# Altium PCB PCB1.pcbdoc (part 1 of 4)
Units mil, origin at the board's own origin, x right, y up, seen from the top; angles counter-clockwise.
Board outline 6180 x 7065 mil, 2 copper layers (Top Layer, Bottom Layer); 471 components, 245 nets, 1464 pads, 505 vias.
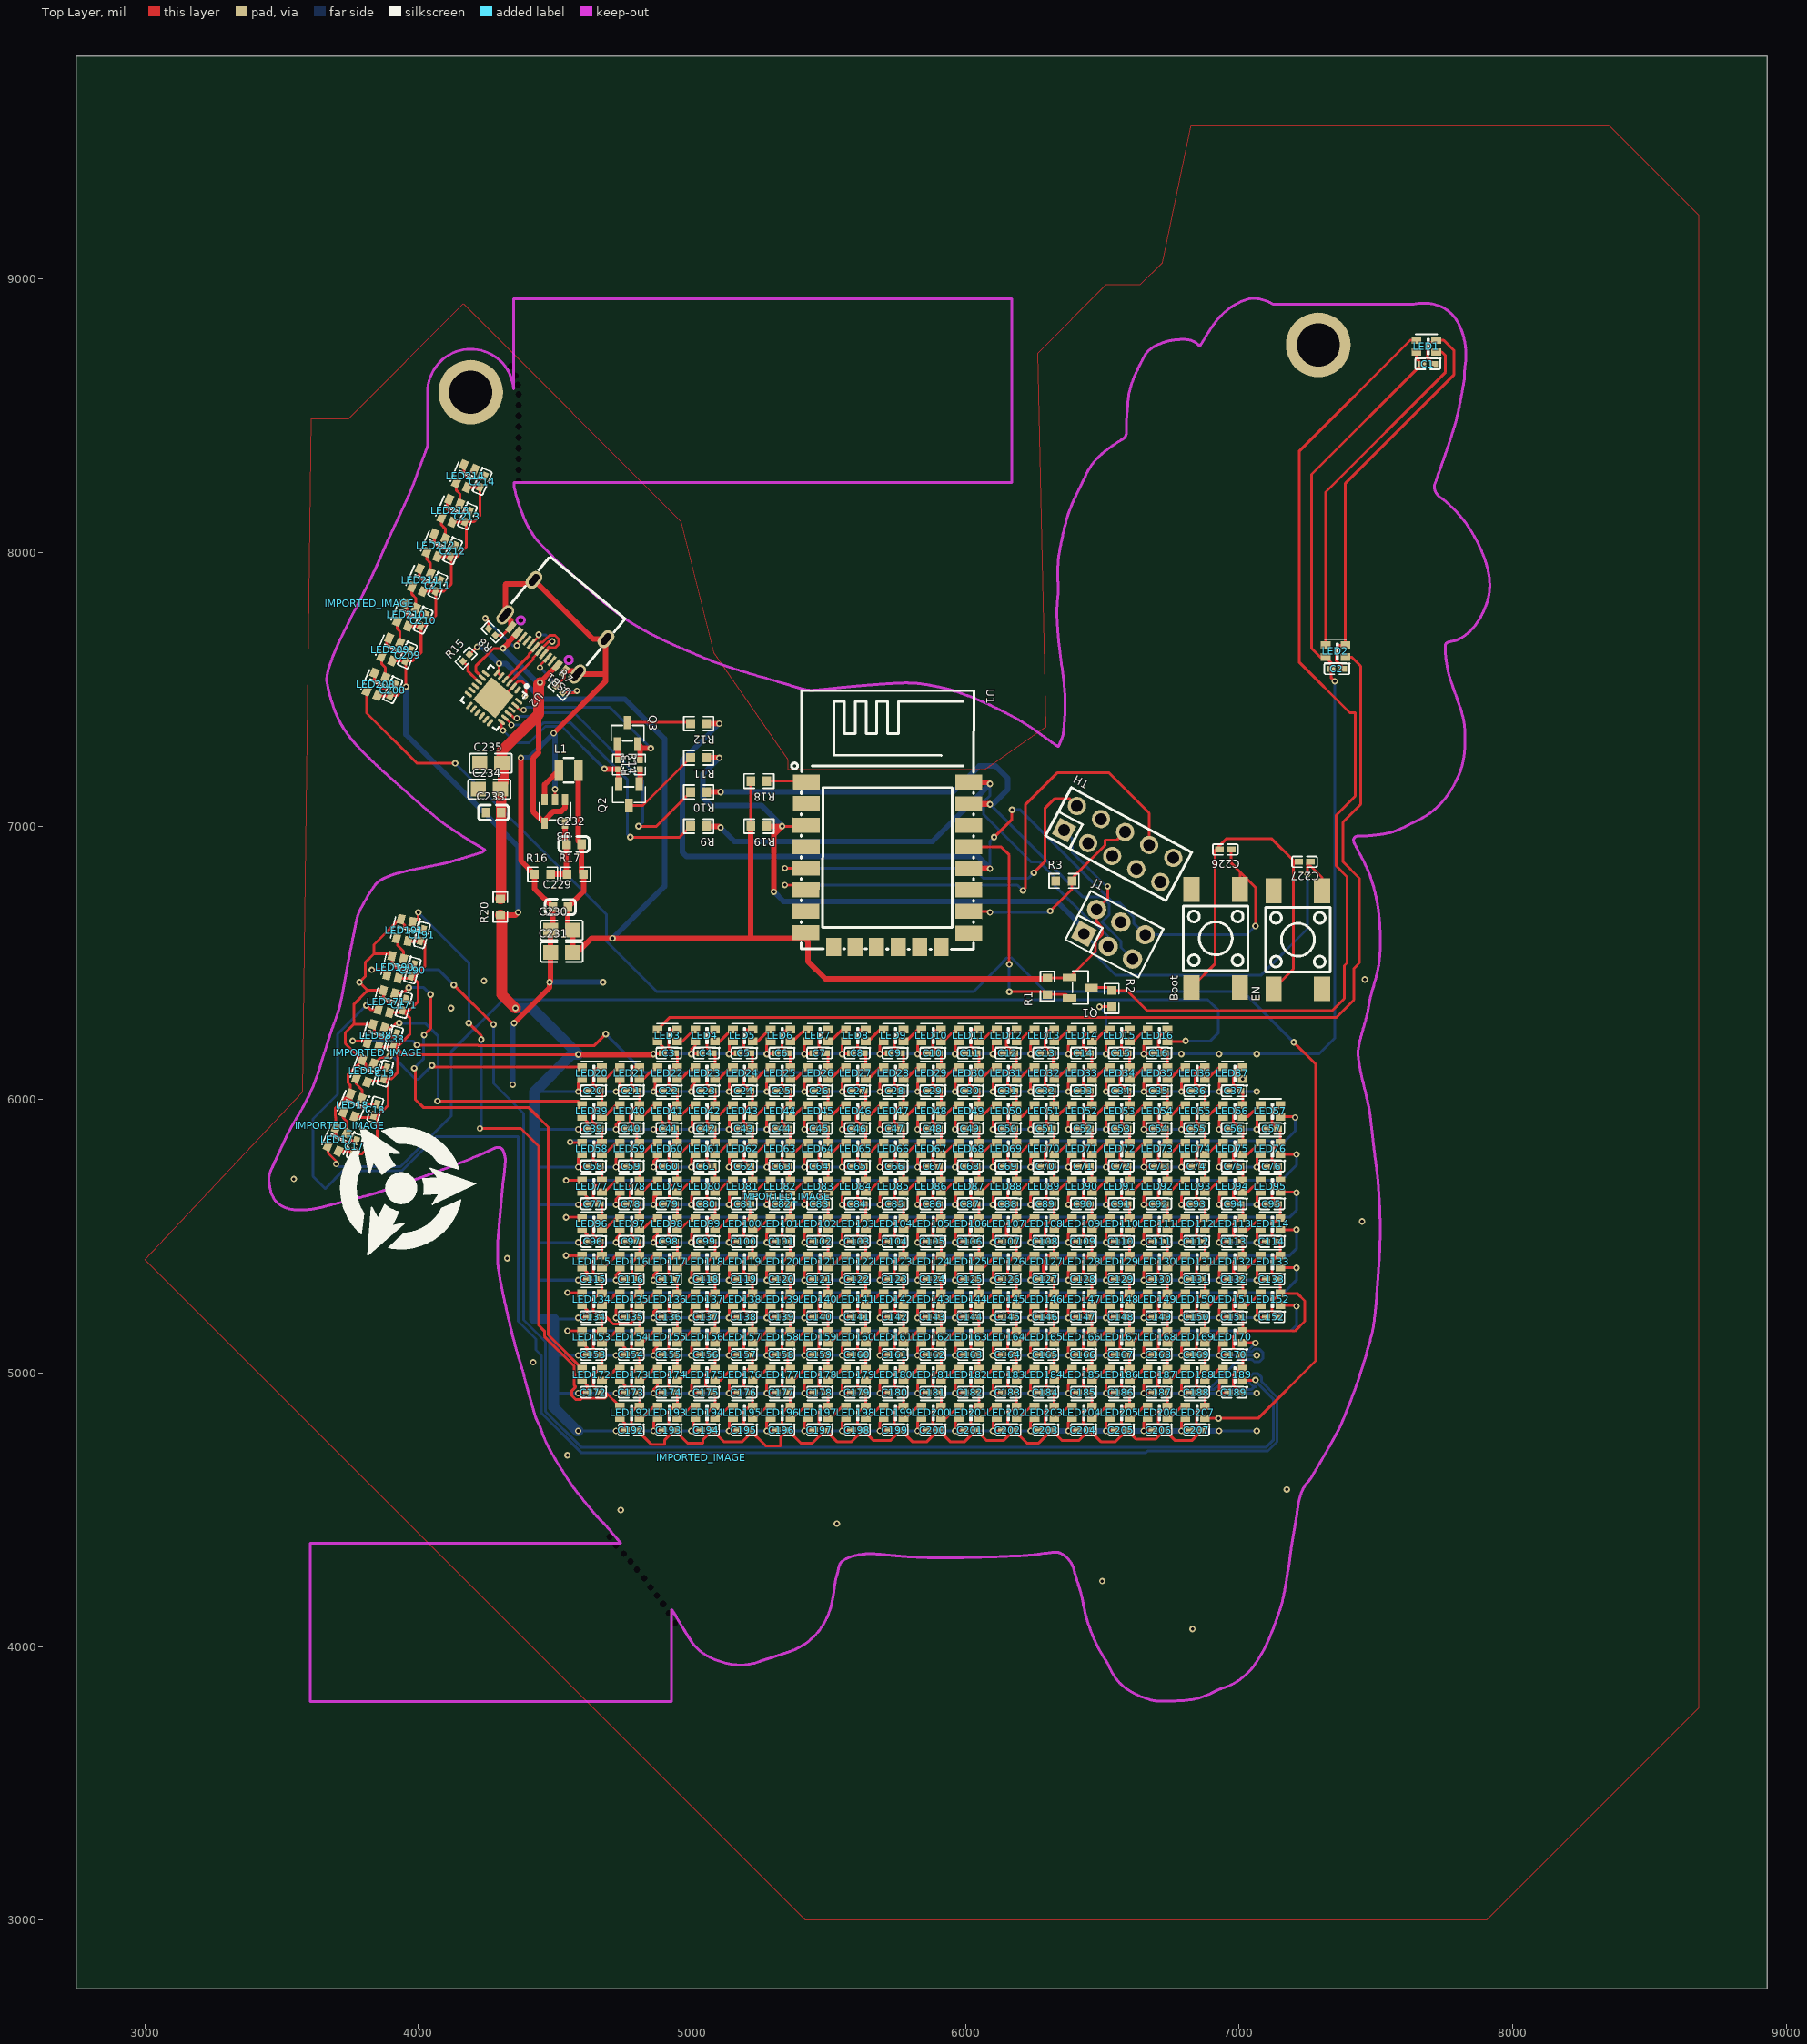
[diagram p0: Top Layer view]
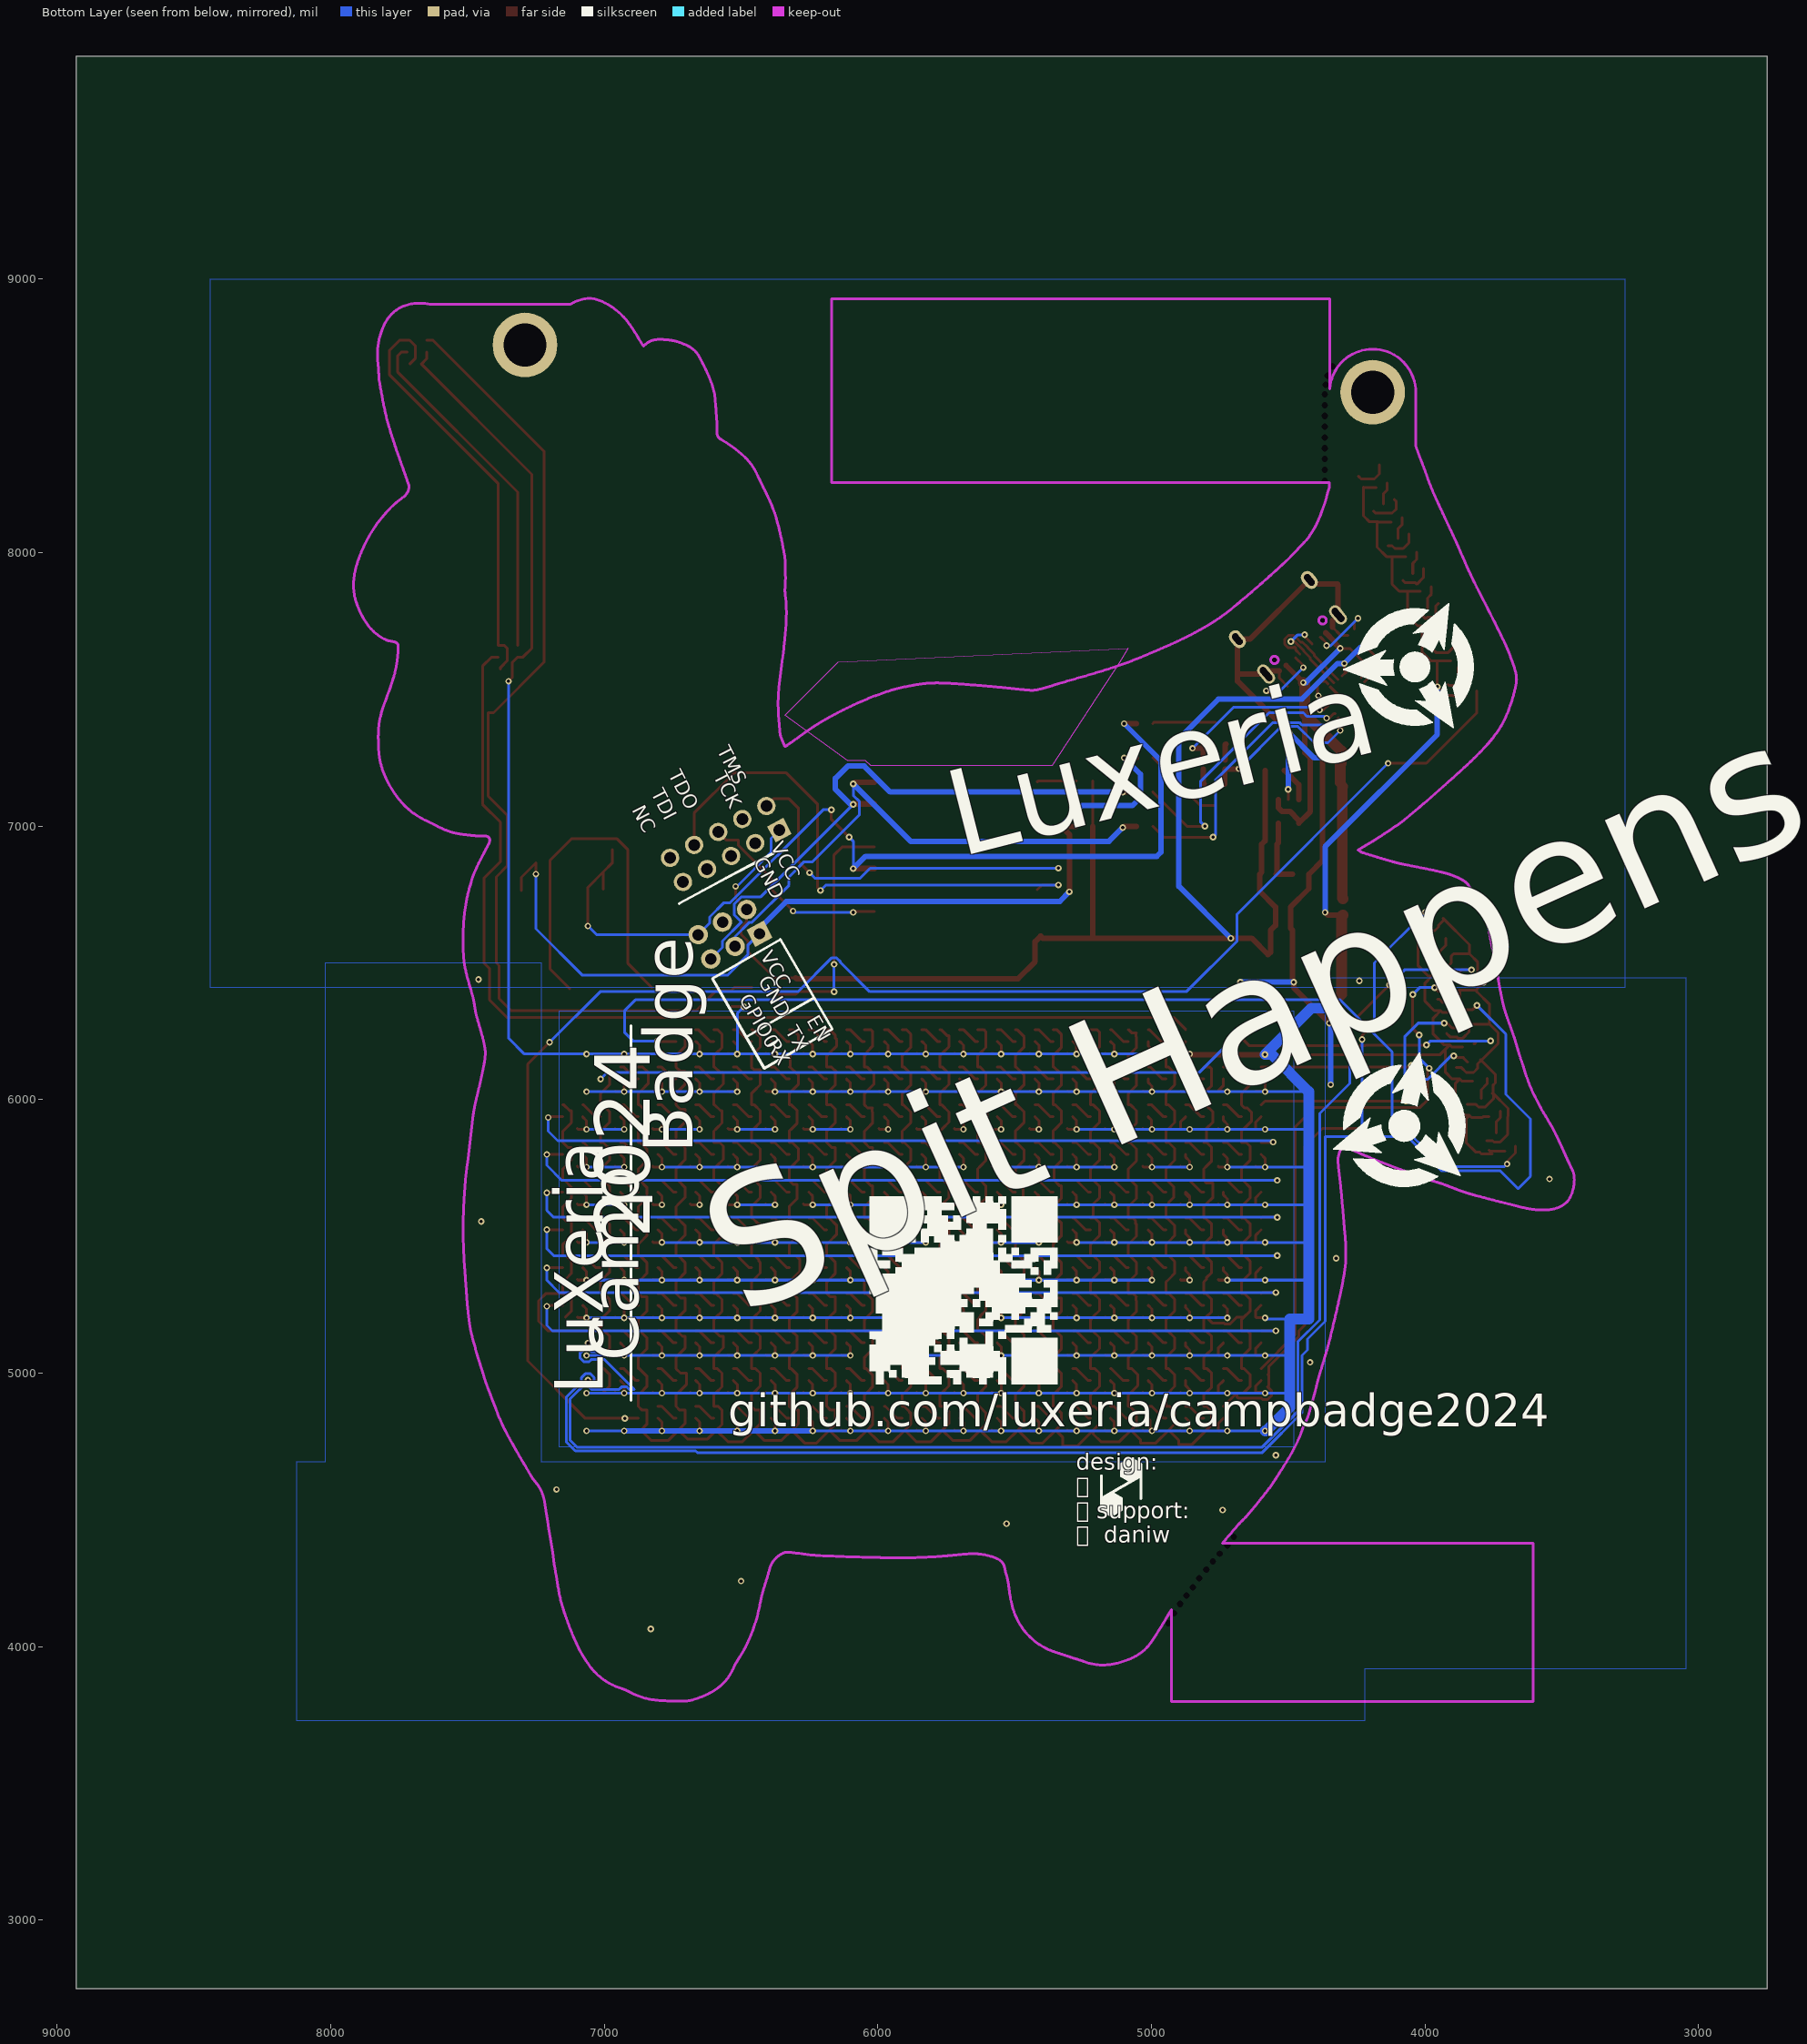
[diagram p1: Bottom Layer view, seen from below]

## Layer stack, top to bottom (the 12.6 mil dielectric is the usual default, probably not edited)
Top Layer: signal copper (thickness not stored)
Dielectric: dielectric 12.6, FR-4, Dk 4.8
Bottom Layer: signal copper (thickness not stored)

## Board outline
8930,2750 2750,2750 2750,9815 8930,9815

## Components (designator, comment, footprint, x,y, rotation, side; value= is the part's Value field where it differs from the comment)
Boot "TS-1002S-04526C" SW-SMD_4P-L6.0-W6.0-P4.50-LS9.0-2 6915,6590 r90 top
C1 "100nF" C0402 7690,8690 r180 top
C2 "CC0402KRX7R5BB104" C0402 7357.8,7575 r180 top
C3 "CC0402KRX7R5BB104" C0402 4915.59,6170 r180 top
C4 "CC0402KRX7R5BB104" C0402 5053.39,6170 r180 top
C5 "CC0402KRX7R5BB104" C0402 5191.18,6170 r180 top
C6 "CC0402KRX7R5BB104" C0402 5328.98,6170 r180 top
C7 "CC0402KRX7R5BB104" C0402 5466.77,6170 r180 top
C8 "CC0402KRX7R5BB104" C0402 5604.57,6170 r180 top
C9 "CC0402KRX7R5BB104" C0402 5742.36,6170 r180 top
C10 "CC0402KRX7R5BB104" C0402 5880.16,6170 r180 top
C11 "CC0402KRX7R5BB104" C0402 6017.95,6170 r180 top
C12 "CC0402KRX7R5BB104" C0402 6155.75,6170 r180 top
C13 "CC0402KRX7R5BB104" C0402 6293.54,6170 r180 top
C14 "CC0402KRX7R5BB104" C0402 6431.34,6170 r180 top
C15 "CC0402KRX7R5BB104" C0402 6569.13,6170 r180 top
C16 "CC0402KRX7R5BB104" C0402 6706.93,6170 r180 top
C17 "CC0402KRX7R5BB104" C0402 3767.86,5829.31 r255 top
C18 "CC0402KRX7R5BB104" C0402 3842.97,5963.18 r255 top
C19 "CC0402KRX7R5BB104" C0402 3878.62,6096.28 r255 top
C20 "CC0402KRX7R5BB104" C0402 4640,6032.2 r180 top
C21 "CC0402KRX7R5BB104" C0402 4777.8,6032.2 r180 top
C22 "CC0402KRX7R5BB104" C0402 4915.59,6032.2 r180 top
C23 "CC0402KRX7R5BB104" C0402 5053.39,6032.2 r180 top
C24 "CC0402KRX7R5BB104" C0402 5191.18,6032.2 r180 top
C25 "CC0402KRX7R5BB104" C0402 5328.98,6032.2 r180 top
C26 "CC0402KRX7R5BB104" C0402 5466.77,6032.2 r180 top
C27 "CC0402KRX7R5BB104" C0402 5604.57,6032.2 r180 top
C28 "CC0402KRX7R5BB104" C0402 5742.36,6032.2 r180 top
C29 "CC0402KRX7R5BB104" C0402 5880.16,6032.2 r180 top
C30 "CC0402KRX7R5BB104" C0402 6017.95,6032.2 r180 top
C31 "CC0402KRX7R5BB104" C0402 6155.75,6032.2 r180 top
C32 "CC0402KRX7R5BB104" C0402 6293.54,6032.2 r180 top
C33 "CC0402KRX7R5BB104" C0402 6431.34,6032.2 r180 top
C34 "CC0402KRX7R5BB104" C0402 6569.13,6032.2 r180 top
C35 "CC0402KRX7R5BB104" C0402 6706.93,6032.2 r180 top
C36 "CC0402KRX7R5BB104" C0402 6844.72,6032.2 r180 top
C37 "CC0402KRX7R5BB104" C0402 6982.52,6032.2 r180 top
C38 "CC0402KRX7R5BB104" C0402 3914.96,6221.13 r255 top
C39 "CC0402KRX7R5BB104" C0402 4640,5894.41 r180 top
C40 "CC0402KRX7R5BB104" C0402 4777.8,5894.41 r180 top
C41 "CC0402KRX7R5BB104" C0402 4915.59,5894.41 r180 top
C42 "CC0402KRX7R5BB104" C0402 5053.39,5894.41 r180 top
C43 "CC0402KRX7R5BB104" C0402 5191.18,5894.41 r180 top
C44 "CC0402KRX7R5BB104" C0402 5328.98,5894.41 r180 top
C45 "CC0402KRX7R5BB104" C0402 5466.77,5894.41 r180 top
C46 "CC0402KRX7R5BB104" C0402 5604.57,5894.41 r180 top
C47 "CC0402KRX7R5BB104" C0402 5742.36,5894.41 r180 top
C48 "CC0402KRX7R5BB104" C0402 5880.16,5894.41 r180 top
C49 "CC0402KRX7R5BB104" C0402 6017.95,5894.41 r180 top
C50 "CC0402KRX7R5BB104" C0402 6155.75,5894.41 r180 top
C51 "CC0402KRX7R5BB104" C0402 6293.54,5894.41 r180 top
C52 "CC0402KRX7R5BB104" C0402 6431.34,5894.41 r180 top
C53 "CC0402KRX7R5BB104" C0402 6569.13,5894.41 r180 top
C54 "CC0402KRX7R5BB104" C0402 6706.93,5894.41 r180 top
C55 "CC0402KRX7R5BB104" C0402 6844.72,5894.41 r180 top
C56 "CC0402KRX7R5BB104" C0402 6982.52,5894.41 r180 top
C57 "CC0402KRX7R5BB104" C0402 7120.31,5894.41 r180 top
C58 "CC0402KRX7R5BB104" C0402 4640,5756.61 r180 top
C59 "CC0402KRX7R5BB104" C0402 4777.8,5756.61 r180 top
C60 "CC0402KRX7R5BB104" C0402 4915.59,5756.61 r180 top
C61 "CC0402KRX7R5BB104" C0402 5053.39,5756.61 r180 top
C62 "CC0402KRX7R5BB104" C0402 5191.18,5756.61 r180 top
C63 "CC0402KRX7R5BB104" C0402 5328.98,5756.61 r180 top
C64 "CC0402KRX7R5BB104" C0402 5466.77,5756.61 r180 top
C65 "CC0402KRX7R5BB104" C0402 5604.57,5756.61 r180 top
C66 "CC0402KRX7R5BB104" C0402 5742.36,5756.61 r180 top
C67 "CC0402KRX7R5BB104" C0402 5880.16,5756.61 r180 top
C68 "CC0402KRX7R5BB104" C0402 6017.95,5756.61 r180 top
C69 "CC0402KRX7R5BB104" C0402 6155.75,5756.61 r180 top
C70 "CC0402KRX7R5BB104" C0402 6293.54,5756.61 r180 top
C71 "CC0402KRX7R5BB104" C0402 6431.34,5756.61 r180 top
C72 "CC0402KRX7R5BB104" C0402 6569.13,5756.61 r180 top
C73 "CC0402KRX7R5BB104" C0402 6706.93,5756.61 r180 top
C74 "CC0402KRX7R5BB104" C0402 6844.72,5756.61 r180 top
C75 "CC0402KRX7R5BB104" C0402 6982.52,5756.61 r180 top
C76 "CC0402KRX7R5BB104" C0402 7120.31,5756.61 r180 top
C77 "CC0402KRX7R5BB104" C0402 4640,5618.82 r180 top
C78 "CC0402KRX7R5BB104" C0402 4777.8,5618.82 r180 top
C79 "CC0402KRX7R5BB104" C0402 4915.59,5618.82 r180 top
C80 "CC0402KRX7R5BB104" C0402 5053.39,5618.82 r180 top
C81 "CC0402KRX7R5BB104" C0402 5191.18,5618.82 r180 top
C82 "CC0402KRX7R5BB104" C0402 5328.98,5618.82 r180 top
C83 "CC0402KRX7R5BB104" C0402 5466.77,5618.82 r180 top
C84 "CC0402KRX7R5BB104" C0402 5604.57,5618.82 r180 top
C85 "CC0402KRX7R5BB104" C0402 5742.36,5618.82 r180 top
C86 "CC0402KRX7R5BB104" C0402 5880.16,5618.82 r180 top
C87 "CC0402KRX7R5BB104" C0402 6017.95,5618.82 r180 top
C88 "CC0402KRX7R5BB104" C0402 6155.75,5618.82 r180 top
C89 "CC0402KRX7R5BB104" C0402 6293.54,5618.82 r180 top
C90 "CC0402KRX7R5BB104" C0402 6431.34,5618.82 r180 top
C91 "CC0402KRX7R5BB104" C0402 6569.13,5618.82 r180 top
C92 "CC0402KRX7R5BB104" C0402 6706.93,5618.82 r180 top
C93 "CC0402KRX7R5BB104" C0402 6844.72,5618.82 r180 top
C94 "CC0402KRX7R5BB104" C0402 6982.52,5618.82 r180 top
C95 "CC0402KRX7R5BB104" C0402 7120.31,5618.82 r180 top
C96 "CC0402KRX7R5BB104" C0402 4640,5481.02 r180 top
C97 "CC0402KRX7R5BB104" C0402 4777.8,5481.02 r180 top
C98 "CC0402KRX7R5BB104" C0402 4915.59,5481.02 r180 top
C99 "CC0402KRX7R5BB104" C0402 5053.39,5481.02 r180 top
C100 "CC0402KRX7R5BB104" C0402 5191.18,5481.02 r180 top
C101 "CC0402KRX7R5BB104" C0402 5328.98,5481.02 r180 top
C102 "CC0402KRX7R5BB104" C0402 5466.77,5481.02 r180 top
C103 "CC0402KRX7R5BB104" C0402 5604.57,5481.02 r180 top
C104 "CC0402KRX7R5BB104" C0402 5742.36,5481.02 r180 top
C105 "CC0402KRX7R5BB104" C0402 5880.16,5481.02 r180 top
C106 "CC0402KRX7R5BB104" C0402 6017.95,5481.02 r180 top
C107 "CC0402KRX7R5BB104" C0402 6155.75,5481.02 r180 top
C108 "CC0402KRX7R5BB104" C0402 6293.54,5481.02 r180 top
C109 "CC0402KRX7R5BB104" C0402 6431.34,5481.02 r180 top
C110 "CC0402KRX7R5BB104" C0402 6569.13,5481.02 r180 top
C111 "CC0402KRX7R5BB104" C0402 6706.93,5481.02 r180 top
C112 "CC0402KRX7R5BB104" C0402 6844.72,5481.02 r180 top
C113 "CC0402KRX7R5BB104" C0402 6982.52,5481.02 r180 top
C114 "CC0402KRX7R5BB104" C0402 7120.31,5481.02 r180 top
C115 "CC0402KRX7R5BB104" C0402 4640,5343.23 r180 top
C116 "CC0402KRX7R5BB104" C0402 4777.8,5343.23 r180 top
C117 "CC0402KRX7R5BB104" C0402 4915.59,5343.23 r180 top
C118 "CC0402KRX7R5BB104" C0402 5053.39,5343.23 r180 top
C119 "CC0402KRX7R5BB104" C0402 5191.18,5343.23 r180 top
C120 "CC0402KRX7R5BB104" C0402 5328.98,5343.23 r180 top
C121 "CC0402KRX7R5BB104" C0402 5466.77,5343.23 r180 top
C122 "CC0402KRX7R5BB104" C0402 5604.57,5343.23 r180 top
C123 "CC0402KRX7R5BB104" C0402 5742.36,5343.23 r180 top
C124 "CC0402KRX7R5BB104" C0402 5880.16,5343.23 r180 top
C125 "CC0402KRX7R5BB104" C0402 6017.95,5343.23 r180 top
C126 "CC0402KRX7R5BB104" C0402 6155.75,5343.23 r180 top
C127 "CC0402KRX7R5BB104" C0402 6293.54,5343.23 r180 top
C128 "CC0402KRX7R5BB104" C0402 6431.34,5343.23 r180 top
C129 "CC0402KRX7R5BB104" C0402 6569.13,5343.23 r180 top
C130 "CC0402KRX7R5BB104" C0402 6706.93,5343.23 r180 top
C131 "CC0402KRX7R5BB104" C0402 6844.72,5343.23 r180 top
C132 "CC0402KRX7R5BB104" C0402 6982.52,5343.23 r180 top
C133 "CC0402KRX7R5BB104" C0402 7120.31,5343.23 r180 top
C134 "CC0402KRX7R5BB104" C0402 4640,5205.43 r180 top
C135 "CC0402KRX7R5BB104" C0402 4777.8,5205.43 r180 top
C136 "CC0402KRX7R5BB104" C0402 4915.59,5205.43 r180 top
C137 "CC0402KRX7R5BB104" C0402 5053.39,5205.43 r180 top
C138 "CC0402KRX7R5BB104" C0402 5191.18,5205.43 r180 top
C139 "CC0402KRX7R5BB104" C0402 5328.98,5205.43 r180 top
C140 "CC0402KRX7R5BB104" C0402 5466.77,5205.43 r180 top
C141 "CC0402KRX7R5BB104" C0402 5604.57,5205.43 r180 top
C142 "CC0402KRX7R5BB104" C0402 5742.36,5205.43 r180 top
C143 "CC0402KRX7R5BB104" C0402 5880.16,5205.43 r180 top
C144 "CC0402KRX7R5BB104" C0402 6017.95,5205.43 r180 top
C145 "CC0402KRX7R5BB104" C0402 6155.75,5205.43 r180 top
C146 "CC0402KRX7R5BB104" C0402 6293.54,5205.43 r180 top
C147 "CC0402KRX7R5BB104" C0402 6431.34,5205.43 r180 top
C148 "CC0402KRX7R5BB104" C0402 6569.13,5205.43 r180 top
C149 "CC0402KRX7R5BB104" C0402 6706.93,5205.43 r180 top
C150 "CC0402KRX7R5BB104" C0402 6844.72,5205.43 r180 top
C151 "CC0402KRX7R5BB104" C0402 6982.52,5205.43 r180 top
C152 "CC0402KRX7R5BB104" C0402 7120.31,5205.43 r180 top
C153 "CC0402KRX7R5BB104" C0402 4640,5067.64 r180 top
C154 "CC0402KRX7R5BB104" C0402 4777.8,5067.64 r180 top
C155 "CC0402KRX7R5BB104" C0402 4915.59,5067.64 r180 top
C156 "CC0402KRX7R5BB104" C0402 5053.39,5067.64 r180 top
C157 "CC0402KRX7R5BB104" C0402 5191.18,5067.64 r180 top
C158 "CC0402KRX7R5BB104" C0402 5328.98,5067.64 r180 top
C159 "CC0402KRX7R5BB104" C0402 5466.77,5067.64 r180 top
C160 "CC0402KRX7R5BB104" C0402 5604.57,5067.64 r180 top
C161 "CC0402KRX7R5BB104" C0402 5742.36,5067.64 r180 top
C162 "CC0402KRX7R5BB104" C0402 5880.16,5067.64 r180 top
C163 "CC0402KRX7R5BB104" C0402 6017.95,5067.64 r180 top
C164 "CC0402KRX7R5BB104" C0402 6155.75,5067.64 r180 top
C165 "CC0402KRX7R5BB104" C0402 6293.54,5067.64 r180 top
C166 "CC0402KRX7R5BB104" C0402 6431.34,5067.64 r180 top
C167 "CC0402KRX7R5BB104" C0402 6569.13,5067.64 r180 top
C168 "CC0402KRX7R5BB104" C0402 6706.93,5067.64 r180 top
C169 "CC0402KRX7R5BB104" C0402 6844.72,5067.64 r180 top
C170 "CC0402KRX7R5BB104" C0402 6982.52,5067.64 r180 top
C171 "CC0402KRX7R5BB104" C0402 3948.18,6346.82 r255 top
C172 "CC0402KRX7R5BB104" C0402 4640,4929.84 r180 top
C173 "CC0402KRX7R5BB104" C0402 4777.8,4929.84 r180 top
C174 "CC0402KRX7R5BB104" C0402 4915.59,4929.84 r180 top
C175 "CC0402KRX7R5BB104" C0402 5053.39,4929.84 r180 top
C176 "CC0402KRX7R5BB104" C0402 5191.18,4929.84 r180 top
C177 "CC0402KRX7R5BB104" C0402 5328.98,4929.84 r180 top
C178 "CC0402KRX7R5BB104" C0402 5466.77,4929.84 r180 top
C179 "CC0402KRX7R5BB104" C0402 5604.57,4929.84 r180 top
C180 "CC0402KRX7R5BB104" C0402 5742.36,4929.84 r180 top
C181 "CC0402KRX7R5BB104" C0402 5880.16,4929.84 r180 top
C182 "CC0402KRX7R5BB104" C0402 6017.95,4929.84 r180 top
C183 "CC0402KRX7R5BB104" C0402 6155.75,4929.84 r180 top
C184 "CC0402KRX7R5BB104" C0402 6293.54,4929.84 r180 top
C185 "CC0402KRX7R5BB104" C0402 6431.34,4929.84 r180 top
C186 "CC0402KRX7R5BB104" C0402 6569.13,4929.84 r180 top
C187 "CC0402KRX7R5BB104" C0402 6706.93,4929.84 r180 top
C188 "CC0402KRX7R5BB104" C0402 6844.72,4929.84 r180 top
C189 "CC0402KRX7R5BB104" C0402 6982.52,4929.84 r180 top
C190 "CC0402KRX7R5BB104" C0402 3979.68,6472.96 r255 top
C191 "CC0402KRX7R5BB104" C0402 4013.53,6602.17 r255 top
C192 "CC0402KRX7R5BB104" C0402 4777.8,4792.05 r180 top
C193 "CC0402KRX7R5BB104" C0402 4915.59,4792.05 r180 top
C194 "CC0402KRX7R5BB104" C0402 5053.39,4792.05 r180 top
C195 "CC0402KRX7R5BB104" C0402 5191.18,4792.05 r180 top
C196 "CC0402KRX7R5BB104" C0402 5328.98,4792.05 r180 top
C197 "CC0402KRX7R5BB104" C0402 5466.77,4792.05 r180 top
C198 "CC0402KRX7R5BB104" C0402 5604.57,4792.05 r180 top
C199 "CC0402KRX7R5BB104" C0402 5742.36,4792.05 r180 top
C200 "CC0402KRX7R5BB104" C0402 5880.16,4792.05 r180 top
C201 "CC0402KRX7R5BB104" C0402 6017.95,4792.05 r180 top
C202 "CC0402KRX7R5BB104" C0402 6155.75,4792.05 r180 top
C203 "CC0402KRX7R5BB104" C0402 6293.54,4792.05 r180 top
C204 "CC0402KRX7R5BB104" C0402 6431.34,4792.05 r180 top
C205 "CC0402KRX7R5BB104" C0402 6569.13,4792.05 r180 top
C206 "CC0402KRX7R5BB104" C0402 6706.93,4792.05 r180 top
C207 "CC0402KRX7R5BB104" C0402 6844.72,4792.05 r180 top
C208 "CC0402KRX7R5BB104" C0402 3907.31,7497.95 r246.96 top
C209 "CC0402KRX7R5BB104" C0402 3961.24,7624.75 r246.96 top
C210 "CC0402KRX7R5BB104" C0402 4018.49,7752.19 r246.96 top
C211 "CC0402KRX7R5BB104" C0402 4072.43,7878.99 r246.96 top
C212 "CC0402KRX7R5BB104" C0402 4126.36,8005.79 r246.96 top
C213 "CC0402KRX7R5BB104" C0402 4180.3,8132.6 r246.96 top
C214 "CC0402KRX7R5BB104" C0402 4234.24,8259.4 r246.96 top
C226 "CL05A105KP5NNNC" C0402 6950,6915 r180 top
C227 "CL05A105KP5NNNC" C0402 7240,6870 r180 top
C229 "CL10A105KB8NNNC" C0603 4519.29,6704.29 r0 top
C230 "CL21A226MAQNNNE" C0805 4524.29,6619.29 r0 top
C231 "CL21A226MAQNNNE" C0805 4524.29,6539.29 r0 top
C232 "CC0603KRX7R9BB102" C0603 4569.29,6934.29 r0 top
C233 "CL10A105KB8NNNC" C0603 4275,7050 r0 top
C234 "CL21A226MAQNNNE" C0805 4260,7135 r0 top
C235 "CL21A226MAQNNNE" C0805 4265,7230 r0 top
EN "TS-1002S-04526C" SW-SMD_4P-L6.0-W6.0-P4.50-LS9.0-2 7215,6585 r90 top
H1 "JTAG" HDR-TH_10P-P2.54-V-M-R2-C5-S2.54 6560,6935 r331.7 top
IMPORTED_IMAGE "IMPORTED_IMAGE" IMPORTED_IMAGE 3821.95,7815.23 r0 top
IMPORTED_IMAGE "IMPORTED_IMAGE" IMPORTED_IMAGE 3852.47,6172.66 r0 top
IMPORTED_IMAGE "IMPORTED_IMAGE" IMPORTED_IMAGE 5034.03,4692.06 r0 top
IMPORTED_IMAGE "IMPORTED_IMAGE" IMPORTED_IMAGE 5343.16,5647.09 r0 top
IMPORTED_IMAGE "IMPORTED_IMAGE" IMPORTED_IMAGE 3714.57,5905.1 r0 top
J1 "Program/Serial" HDR-TH_6P-P2.54-V-M-R2-C3-S2.54-1 6545,6605 r332.53 top
L1 "WIP201610P-2R2ML" IND-SMD_L2.0-W1.6_MHCHL201610A-1R0M-Q8A 4549.29,7204.29 r0 top
LED1 "WS2812C-2020-V1" LED-SMD_4P-L2.0-W2.0-TL_WS2812B-2020 7685,8755 r180 top
LED2 "WS2812C-2020-V1" LED-SMD_4P-L2.0-W2.0-TL_WS2812B-2020 7352.8,7640 r180 top
LED3 "WS2812C-2020-V1" LED-SMD_4P-L2.0-W2.0-TL_WS2812B-2020 4910.59,6235 r180 top
LED4 "WS2812C-2020-V1" LED-SMD_4P-L2.0-W2.0-TL_WS2812B-2020 5048.39,6235 r180 top
LED5 "WS2812C-2020-V1" LED-SMD_4P-L2.0-W2.0-TL_WS2812B-2020 5186.18,6235 r180 top
LED6 "WS2812C-2020-V1" LED-SMD_4P-L2.0-W2.0-TL_WS2812B-2020 5323.98,6235 r180 top
LED7 "WS2812C-2020-V1" LED-SMD_4P-L2.0-W2.0-TL_WS2812B-2020 5461.77,6235 r180 top
LED8 "WS2812C-2020-V1" LED-SMD_4P-L2.0-W2.0-TL_WS2812B-2020 5599.57,6235 r180 top
LED9 "WS2812C-2020-V1" LED-SMD_4P-L2.0-W2.0-TL_WS2812B-2020 5737.36,6235 r180 top
LED10 "WS2812C-2020-V1" LED-SMD_4P-L2.0-W2.0-TL_WS2812B-2020 5875.16,6235 r180 top
LED11 "WS2812C-2020-V1" LED-SMD_4P-L2.0-W2.0-TL_WS2812B-2020 6012.95,6235 r180 top
LED12 "WS2812C-2020-V1" LED-SMD_4P-L2.0-W2.0-TL_WS2812B-2020 6150.75,6235 r180 top
LED13 "WS2812C-2020-V1" LED-SMD_4P-L2.0-W2.0-TL_WS2812B-2020 6288.54,6235 r180 top
LED14 "WS2812C-2020-V1" LED-SMD_4P-L2.0-W2.0-TL_WS2812B-2020 6426.34,6235 r180 top
LED15 "WS2812C-2020-V1" LED-SMD_4P-L2.0-W2.0-TL_WS2812B-2020 6564.13,6235 r180 top
LED16 "WS2812C-2020-V1" LED-SMD_4P-L2.0-W2.0-TL_WS2812B-2020 6701.93,6235 r180 top
LED17 "WS2812C-2020-V1" LED-SMD_4P-L2.0-W2.0-TL_WS2812B-2020 3703.81,5854.42 r245.4 top
LED18 "WS2812C-2020-V1" LED-SMD_4P-L2.0-W2.0-TL_WS2812B-2020 3760.01,5980.28 r247.93 top
LED19 "WS2812C-2020-V1" LED-SMD_4P-L2.0-W2.0-TL_WS2812B-2020 3805,6105 r250.87 top
LED20 "WS2812C-2020-V1" LED-SMD_4P-L2.0-W2.0-TL_WS2812B-2020 4635,6097.2 r180 top
LED21 "WS2812C-2020-V1" LED-SMD_4P-L2.0-W2.0-TL_WS2812B-2020 4772.8,6097.2 r180 top
LED22 "WS2812C-2020-V1" LED-SMD_4P-L2.0-W2.0-TL_WS2812B-2020 4910.59,6097.2 r180 top
LED23 "WS2812C-2020-V1" LED-SMD_4P-L2.0-W2.0-TL_WS2812B-2020 5048.39,6097.2 r180 top
LED24 "WS2812C-2020-V1" LED-SMD_4P-L2.0-W2.0-TL_WS2812B-2020 5186.18,6097.2 r180 top
LED25 "WS2812C-2020-V1" LED-SMD_4P-L2.0-W2.0-TL_WS2812B-2020 5323.98,6097.2 r180 top
LED26 "WS2812C-2020-V1" LED-SMD_4P-L2.0-W2.0-TL_WS2812B-2020 5461.77,6097.2 r180 top
LED27 "WS2812C-2020-V1" LED-SMD_4P-L2.0-W2.0-TL_WS2812B-2020 5599.57,6097.2 r180 top
LED28 "WS2812C-2020-V1" LED-SMD_4P-L2.0-W2.0-TL_WS2812B-2020 5737.36,6097.2 r180 top
LED29 "WS2812C-2020-V1" LED-SMD_4P-L2.0-W2.0-TL_WS2812B-2020 5875.16,6097.2 r180 top
LED30 "WS2812C-2020-V1" LED-SMD_4P-L2.0-W2.0-TL_WS2812B-2020 6012.95,6097.2 r180 top
LED31 "WS2812C-2020-V1" LED-SMD_4P-L2.0-W2.0-TL_WS2812B-2020 6150.75,6097.2 r180 top
LED32 "WS2812C-2020-V1" LED-SMD_4P-L2.0-W2.0-TL_WS2812B-2020 6288.54,6097.2 r180 top
LED33 "WS2812C-2020-V1" LED-SMD_4P-L2.0-W2.0-TL_WS2812B-2020 6426.34,6097.2 r180 top
LED34 "WS2812C-2020-V1" LED-SMD_4P-L2.0-W2.0-TL_WS2812B-2020 6564.13,6097.2 r180 top
LED35 "WS2812C-2020-V1" LED-SMD_4P-L2.0-W2.0-TL_WS2812B-2020 6701.93,6097.2 r180 top
LED36 "WS2812C-2020-V1" LED-SMD_4P-L2.0-W2.0-TL_WS2812B-2020 6839.72,6097.2 r180 top
LED37 "WS2812C-2020-V1" LED-SMD_4P-L2.0-W2.0-TL_WS2812B-2020 6977.52,6097.2 r180 top
LED38 "WS2812C-2020-V1" LED-SMD_4P-L2.0-W2.0-TL_WS2812B-2020 3845,6235 r253.06 top
LED39 "WS2812C-2020-V1" LED-SMD_4P-L2.0-W2.0-TL_WS2812B-2020 4635,5959.41 r180 top
LED40 "WS2812C-2020-V1" LED-SMD_4P-L2.0-W2.0-TL_WS2812B-2020 4772.8,5959.41 r180 top
LED41 "WS2812C-2020-V1" LED-SMD_4P-L2.0-W2.0-TL_WS2812B-2020 4910.59,5959.41 r180 top
LED42 "WS2812C-2020-V1" LED-SMD_4P-L2.0-W2.0-TL_WS2812B-2020 5048.39,5959.41 r180 top
LED43 "WS2812C-2020-V1" LED-SMD_4P-L2.0-W2.0-TL_WS2812B-2020 5186.18,5959.41 r180 top
LED44 "WS2812C-2020-V1" LED-SMD_4P-L2.0-W2.0-TL_WS2812B-2020 5323.98,5959.41 r180 top
LED45 "WS2812C-2020-V1" LED-SMD_4P-L2.0-W2.0-TL_WS2812B-2020 5461.77,5959.41 r180 top
LED46 "WS2812C-2020-V1" LED-SMD_4P-L2.0-W2.0-TL_WS2812B-2020 5599.57,5959.41 r180 top
LED47 "WS2812C-2020-V1" LED-SMD_4P-L2.0-W2.0-TL_WS2812B-2020 5737.36,5959.41 r180 top
LED48 "WS2812C-2020-V1" LED-SMD_4P-L2.0-W2.0-TL_WS2812B-2020 5875.16,5959.41 r180 top
LED49 "WS2812C-2020-V1" LED-SMD_4P-L2.0-W2.0-TL_WS2812B-2020 6012.95,5959.41 r180 top
LED50 "WS2812C-2020-V1" LED-SMD_4P-L2.0-W2.0-TL_WS2812B-2020 6150.75,5959.41 r180 top
LED51 "WS2812C-2020-V1" LED-SMD_4P-L2.0-W2.0-TL_WS2812B-2020 6288.54,5959.41 r180 top
LED52 "WS2812C-2020-V1" LED-SMD_4P-L2.0-W2.0-TL_WS2812B-2020 6426.34,5959.41 r180 top
LED53 "WS2812C-2020-V1" LED-SMD_4P-L2.0-W2.0-TL_WS2812B-2020 6564.13,5959.41 r180 top
LED54 "WS2812C-2020-V1" LED-SMD_4P-L2.0-W2.0-TL_WS2812B-2020 6701.93,5959.41 r180 top
LED55 "WS2812C-2020-V1" LED-SMD_4P-L2.0-W2.0-TL_WS2812B-2020 6839.72,5959.41 r180 top
LED56 "WS2812C-2020-V1" LED-SMD_4P-L2.0-W2.0-TL_WS2812B-2020 6977.52,5959.41 r180 top
LED57 "WS2812C-2020-V1" LED-SMD_4P-L2.0-W2.0-TL_WS2812B-2020 7115.31,5959.41 r180 top
LED58 "WS2812C-2020-V1" LED-SMD_4P-L2.0-W2.0-TL_WS2812B-2020 4635,5821.61 r180 top
LED59 "WS2812C-2020-V1" LED-SMD_4P-L2.0-W2.0-TL_WS2812B-2020 4772.8,5821.61 r180 top
LED60 "WS2812C-2020-V1" LED-SMD_4P-L2.0-W2.0-TL_WS2812B-2020 4910.59,5821.61 r180 top
LED61 "WS2812C-2020-V1" LED-SMD_4P-L2.0-W2.0-TL_WS2812B-2020 5048.39,5821.61 r180 top
LED62 "WS2812C-2020-V1" LED-SMD_4P-L2.0-W2.0-TL_WS2812B-2020 5186.18,5821.61 r180 top
LED63 "WS2812C-2020-V1" LED-SMD_4P-L2.0-W2.0-TL_WS2812B-2020 5323.98,5821.61 r180 top
LED64 "WS2812C-2020-V1" LED-SMD_4P-L2.0-W2.0-TL_WS2812B-2020 5461.77,5821.61 r180 top
LED65 "WS2812C-2020-V1" LED-SMD_4P-L2.0-W2.0-TL_WS2812B-2020 5599.57,5821.61 r180 top
LED66 "WS2812C-2020-V1" LED-SMD_4P-L2.0-W2.0-TL_WS2812B-2020 5737.36,5821.61 r180 top
LED67 "WS2812C-2020-V1" LED-SMD_4P-L2.0-W2.0-TL_WS2812B-2020 5875.16,5821.61 r180 top
LED68 "WS2812C-2020-V1" LED-SMD_4P-L2.0-W2.0-TL_WS2812B-2020 6012.95,5821.61 r180 top
LED69 "WS2812C-2020-V1" LED-SMD_4P-L2.0-W2.0-TL_WS2812B-2020 6150.75,5821.61 r180 top
LED70 "WS2812C-2020-V1" LED-SMD_4P-L2.0-W2.0-TL_WS2812B-2020 6288.54,5821.61 r180 top
LED71 "WS2812C-2020-V1" LED-SMD_4P-L2.0-W2.0-TL_WS2812B-2020 6426.34,5821.61 r180 top
LED72 "WS2812C-2020-V1" LED-SMD_4P-L2.0-W2.0-TL_WS2812B-2020 6564.13,5821.61 r180 top
LED73 "WS2812C-2020-V1" LED-SMD_4P-L2.0-W2.0-TL_WS2812B-2020 6701.93,5821.61 r180 top
LED74 "WS2812C-2020-V1" LED-SMD_4P-L2.0-W2.0-TL_WS2812B-2020 6839.72,5821.61 r180 top
LED75 "WS2812C-2020-V1" LED-SMD_4P-L2.0-W2.0-TL_WS2812B-2020 6977.52,5821.61 r180 top
LED76 "WS2812C-2020-V1" LED-SMD_4P-L2.0-W2.0-TL_WS2812B-2020 7115.31,5821.61 r180 top
LED77 "WS2812C-2020-V1" LED-SMD_4P-L2.0-W2.0-TL_WS2812B-2020 4635,5683.82 r180 top
LED78 "WS2812C-2020-V1" LED-SMD_4P-L2.0-W2.0-TL_WS2812B-2020 4772.8,5683.82 r180 top
LED79 "WS2812C-2020-V1" LED-SMD_4P-L2.0-W2.0-TL_WS2812B-2020 4910.59,5683.82 r180 top
LED80 "WS2812C-2020-V1" LED-SMD_4P-L2.0-W2.0-TL_WS2812B-2020 5048.39,5683.82 r180 top
LED81 "WS2812C-2020-V1" LED-SMD_4P-L2.0-W2.0-TL_WS2812B-2020 5186.18,5683.82 r180 top
LED82 "WS2812C-2020-V1" LED-SMD_4P-L2.0-W2.0-TL_WS2812B-2020 5323.98,5683.82 r180 top
LED83 "WS2812C-2020-V1" LED-SMD_4P-L2.0-W2.0-TL_WS2812B-2020 5461.77,5683.82 r180 top
LED84 "WS2812C-2020-V1" LED-SMD_4P-L2.0-W2.0-TL_WS2812B-2020 5599.57,5683.82 r180 top
LED85 "WS2812C-2020-V1" LED-SMD_4P-L2.0-W2.0-TL_WS2812B-2020 5737.36,5683.82 r180 top
LED86 "WS2812C-2020-V1" LED-SMD_4P-L2.0-W2.0-TL_WS2812B-2020 5875.16,5683.82 r180 top
LED87 "WS2812C-2020-V1" LED-SMD_4P-L2.0-W2.0-TL_WS2812B-2020 6012.95,5683.82 r180 top
LED88 "WS2812C-2020-V1" LED-SMD_4P-L2.0-W2.0-TL_WS2812B-2020 6150.75,5683.82 r180 top
LED89 "WS2812C-2020-V1" LED-SMD_4P-L2.0-W2.0-TL_WS2812B-2020 6288.54,5683.82 r180 top
LED90 "WS2812C-2020-V1" LED-SMD_4P-L2.0-W2.0-TL_WS2812B-2020 6426.34,5683.82 r180 top
LED91 "WS2812C-2020-V1" LED-SMD_4P-L2.0-W2.0-TL_WS2812B-2020 6564.13,5683.82 r180 top
LED92 "WS2812C-2020-V1" LED-SMD_4P-L2.0-W2.0-TL_WS2812B-2020 6701.93,5683.82 r180 top
LED93 "WS2812C-2020-V1" LED-SMD_4P-L2.0-W2.0-TL_WS2812B-2020 6839.72,5683.82 r180 top
LED94 "WS2812C-2020-V1" LED-SMD_4P-L2.0-W2.0-TL_WS2812B-2020 6977.52,5683.82 r180 top
LED95 "WS2812C-2020-V1" LED-SMD_4P-L2.0-W2.0-TL_WS2812B-2020 7115.31,5683.82 r180 top
LED96 "WS2812C-2020-V1" LED-SMD_4P-L2.0-W2.0-TL_WS2812B-2020 4635,5546.02 r180 top
LED97 "WS2812C-2020-V1" LED-SMD_4P-L2.0-W2.0-TL_WS2812B-2020 4772.8,5546.02 r180 top
LED98 "WS2812C-2020-V1" LED-SMD_4P-L2.0-W2.0-TL_WS2812B-2020 4910.59,5546.02 r180 top
LED99 "WS2812C-2020-V1" LED-SMD_4P-L2.0-W2.0-TL_WS2812B-2020 5048.39,5546.02 r180 top
LED100 "WS2812C-2020-V1" LED-SMD_4P-L2.0-W2.0-TL_WS2812B-2020 5186.18,5546.02 r180 top
LED101 "WS2812C-2020-V1" LED-SMD_4P-L2.0-W2.0-TL_WS2812B-2020 5323.98,5546.02 r180 top
LED102 "WS2812C-2020-V1" LED-SMD_4P-L2.0-W2.0-TL_WS2812B-2020 5461.77,5546.02 r180 top
LED103 "WS2812C-2020-V1" LED-SMD_4P-L2.0-W2.0-TL_WS2812B-2020 5599.57,5546.02 r180 top
LED104 "WS2812C-2020-V1" LED-SMD_4P-L2.0-W2.0-TL_WS2812B-2020 5737.36,5546.02 r180 top
LED105 "WS2812C-2020-V1" LED-SMD_4P-L2.0-W2.0-TL_WS2812B-2020 5875.16,5546.02 r180 top
LED106 "WS2812C-2020-V1" LED-SMD_4P-L2.0-W2.0-TL_WS2812B-2020 6012.95,5546.02 r180 top
LED107 "WS2812C-2020-V1" LED-SMD_4P-L2.0-W2.0-TL_WS2812B-2020 6150.75,5546.02 r180 top
LED108 "WS2812C-2020-V1" LED-SMD_4P-L2.0-W2.0-TL_WS2812B-2020 6288.54,5546.02 r180 top
LED109 "WS2812C-2020-V1" LED-SMD_4P-L2.0-W2.0-TL_WS2812B-2020 6426.34,5546.02 r180 top
LED110 "WS2812C-2020-V1" LED-SMD_4P-L2.0-W2.0-TL_WS2812B-2020 6564.13,5546.02 r180 top
LED111 "WS2812C-2020-V1" LED-SMD_4P-L2.0-W2.0-TL_WS2812B-2020 6701.93,5546.02 r180 top
LED112 "WS2812C-2020-V1" LED-SMD_4P-L2.0-W2.0-TL_WS2812B-2020 6839.72,5546.02 r180 top
LED113 "WS2812C-2020-V1" LED-SMD_4P-L2.0-W2.0-TL_WS2812B-2020 6977.52,5546.02 r180 top
LED114 "WS2812C-2020-V1" LED-SMD_4P-L2.0-W2.0-TL_WS2812B-2020 7115.31,5546.02 r180 top
LED115 "WS2812C-2020-V1" LED-SMD_4P-L2.0-W2.0-TL_WS2812B-2020 4635,5408.23 r180 top
LED116 "WS2812C-2020-V1" LED-SMD_4P-L2.0-W2.0-TL_WS2812B-2020 4772.8,5408.23 r180 top
LED117 "WS2812C-2020-V1" LED-SMD_4P-L2.0-W2.0-TL_WS2812B-2020 4910.59,5408.23 r180 top
LED118 "WS2812C-2020-V1" LED-SMD_4P-L2.0-W2.0-TL_WS2812B-2020 5048.39,5408.23 r180 top
LED119 "WS2812C-2020-V1" LED-SMD_4P-L2.0-W2.0-TL_WS2812B-2020 5186.18,5408.23 r180 top
LED120 "WS2812C-2020-V1" LED-SMD_4P-L2.0-W2.0-TL_WS2812B-2020 5323.98,5408.23 r180 top
LED121 "WS2812C-2020-V1" LED-SMD_4P-L2.0-W2.0-TL_WS2812B-2020 5461.77,5408.23 r180 top
LED122 "WS2812C-2020-V1" LED-SMD_4P-L2.0-W2.0-TL_WS2812B-2020 5599.57,5408.23 r180 top
LED123 "WS2812C-2020-V1" LED-SMD_4P-L2.0-W2.0-TL_WS2812B-2020 5737.36,5408.23 r180 top
LED124 "WS2812C-2020-V1" LED-SMD_4P-L2.0-W2.0-TL_WS2812B-2020 5875.16,5408.23 r180 top
LED125 "WS2812C-2020-V1" LED-SMD_4P-L2.0-W2.0-TL_WS2812B-2020 6012.95,5408.23 r180 top
LED126 "WS2812C-2020-V1" LED-SMD_4P-L2.0-W2.0-TL_WS2812B-2020 6150.75,5408.23 r180 top
LED127 "WS2812C-2020-V1" LED-SMD_4P-L2.0-W2.0-TL_WS2812B-2020 6288.54,5408.23 r180 top
LED128 "WS2812C-2020-V1" LED-SMD_4P-L2.0-W2.0-TL_WS2812B-2020 6426.34,5408.23 r180 top
LED129 "WS2812C-2020-V1" LED-SMD_4P-L2.0-W2.0-TL_WS2812B-2020 6564.13,5408.23 r180 top
LED130 "WS2812C-2020-V1" LED-SMD_4P-L2.0-W2.0-TL_WS2812B-2020 6701.93,5408.23 r180 top
LED131 "WS2812C-2020-V1" LED-SMD_4P-L2.0-W2.0-TL_WS2812B-2020 6839.72,5408.23 r180 top
LED132 "WS2812C-2020-V1" LED-SMD_4P-L2.0-W2.0-TL_WS2812B-2020 6977.52,5408.23 r180 top
LED133 "WS2812C-2020-V1" LED-SMD_4P-L2.0-W2.0-TL_WS2812B-2020 7115.31,5408.23 r180 top
LED134 "WS2812C-2020-V1" LED-SMD_4P-L2.0-W2.0-TL_WS2812B-2020 4635,5270.43 r180 top
LED135 "WS2812C-2020-V1" LED-SMD_4P-L2.0-W2.0-TL_WS2812B-2020 4772.8,5270.43 r180 top
LED136 "WS2812C-2020-V1" LED-SMD_4P-L2.0-W2.0-TL_WS2812B-2020 4910.59,5270.43 r180 top
LED137 "WS2812C-2020-V1" LED-SMD_4P-L2.0-W2.0-TL_WS2812B-2020 5048.39,5270.43 r180 top
LED138 "WS2812C-2020-V1" LED-SMD_4P-L2.0-W2.0-TL_WS2812B-2020 5186.18,5270.43 r180 top
LED139 "WS2812C-2020-V1" LED-SMD_4P-L2.0-W2.0-TL_WS2812B-2020 5323.98,5270.43 r180 top
LED140 "WS2812C-2020-V1" LED-SMD_4P-L2.0-W2.0-TL_WS2812B-2020 5461.77,5270.43 r180 top
LED141 "WS2812C-2020-V1" LED-SMD_4P-L2.0-W2.0-TL_WS2812B-2020 5599.57,5270.43 r180 top
LED142 "WS2812C-2020-V1" LED-SMD_4P-L2.0-W2.0-TL_WS2812B-2020 5737.36,5270.43 r180 top
LED143 "WS2812C-2020-V1" LED-SMD_4P-L2.0-W2.0-TL_WS2812B-2020 5875.16,5270.43 r180 top
LED144 "WS2812C-2020-V1" LED-SMD_4P-L2.0-W2.0-TL_WS2812B-2020 6012.95,5270.43 r180 top
LED145 "WS2812C-2020-V1" LED-SMD_4P-L2.0-W2.0-TL_WS2812B-2020 6150.75,5270.43 r180 top
LED146 "WS2812C-2020-V1" LED-SMD_4P-L2.0-W2.0-TL_WS2812B-2020 6288.54,5270.43 r180 top
LED147 "WS2812C-2020-V1" LED-SMD_4P-L2.0-W2.0-TL_WS2812B-2020 6426.34,5270.43 r180 top
LED148 "WS2812C-2020-V1" LED-SMD_4P-L2.0-W2.0-TL_WS2812B-2020 6564.13,5270.43 r180 top
LED149 "WS2812C-2020-V1" LED-SMD_4P-L2.0-W2.0-TL_WS2812B-2020 6701.93,5270.43 r180 top
LED150 "WS2812C-2020-V1" LED-SMD_4P-L2.0-W2.0-TL_WS2812B-2020 6839.72,5270.43 r180 top
LED151 "WS2812C-2020-V1" LED-SMD_4P-L2.0-W2.0-TL_WS2812B-2020 6977.52,5270.43 r180 top
LED152 "WS2812C-2020-V1" LED-SMD_4P-L2.0-W2.0-TL_WS2812B-2020 7115.31,5270.43 r180 top
LED153 "WS2812C-2020-V1" LED-SMD_4P-L2.0-W2.0-TL_WS2812B-2020 4635,5132.64 r180 top
LED154 "WS2812C-2020-V1" LED-SMD_4P-L2.0-W2.0-TL_WS2812B-2020 4772.8,5132.64 r180 top
LED155 "WS2812C-2020-V1" LED-SMD_4P-L2.0-W2.0-TL_WS2812B-2020 4910.59,5132.64 r180 top
LED156 "WS2812C-2020-V1" LED-SMD_4P-L2.0-W2.0-TL_WS2812B-2020 5048.39,5132.64 r180 top
LED157 "WS2812C-2020-V1" LED-SMD_4P-L2.0-W2.0-TL_WS2812B-2020 5186.18,5132.64 r180 top
LED158 "WS2812C-2020-V1" LED-SMD_4P-L2.0-W2.0-TL_WS2812B-2020 5323.98,5132.64 r180 top
LED159 "WS2812C-2020-V1" LED-SMD_4P-L2.0-W2.0-TL_WS2812B-2020 5461.77,5132.64 r180 top
LED160 "WS2812C-2020-V1" LED-SMD_4P-L2.0-W2.0-TL_WS2812B-2020 5599.57,5132.64 r180 top
LED161 "WS2812C-2020-V1" LED-SMD_4P-L2.0-W2.0-TL_WS2812B-2020 5737.36,5132.64 r180 top
LED162 "WS2812C-2020-V1" LED-SMD_4P-L2.0-W2.0-TL_WS2812B-2020 5875.16,5132.64 r180 top
LED163 "WS2812C-2020-V1" LED-SMD_4P-L2.0-W2.0-TL_WS2812B-2020 6012.95,5132.64 r180 top
LED164 "WS2812C-2020-V1" LED-SMD_4P-L2.0-W2.0-TL_WS2812B-2020 6150.75,5132.64 r180 top
LED165 "WS2812C-2020-V1" LED-SMD_4P-L2.0-W2.0-TL_WS2812B-2020 6288.54,5132.64 r180 top
LED166 "WS2812C-2020-V1" LED-SMD_4P-L2.0-W2.0-TL_WS2812B-2020 6426.34,5132.64 r180 top
LED167 "WS2812C-2020-V1" LED-SMD_4P-L2.0-W2.0-TL_WS2812B-2020 6564.13,5132.64 r180 top
LED168 "WS2812C-2020-V1" LED-SMD_4P-L2.0-W2.0-TL_WS2812B-2020 6701.93,5132.64 r180 top
LED169 "WS2812C-2020-V1" LED-SMD_4P-L2.0-W2.0-TL_WS2812B-2020 6839.72,5132.64 r180 top
LED170 "WS2812C-2020-V1" LED-SMD_4P-L2.0-W2.0-TL_WS2812B-2020 6977.52,5132.64 r180 top
LED171 "WS2812C-2020-V1" LED-SMD_4P-L2.0-W2.0-TL_WS2812B-2020 3884.1,6358.81 r255 top
LED172 "WS2812C-2020-V1" LED-SMD_4P-L2.0-W2.0-TL_WS2812B-2020 4635,4994.84 r180 top
LED173 "WS2812C-2020-V1" LED-SMD_4P-L2.0-W2.0-TL_WS2812B-2020 4772.8,4994.84 r180 top
LED174 "WS2812C-2020-V1" LED-SMD_4P-L2.0-W2.0-TL_WS2812B-2020 4910.59,4994.84 r180 top
LED175 "WS2812C-2020-V1" LED-SMD_4P-L2.0-W2.0-TL_WS2812B-2020 5048.39,4994.84 r180 top
LED176 "WS2812C-2020-V1" LED-SMD_4P-L2.0-W2.0-TL_WS2812B-2020 5186.18,4994.84 r180 top
LED177 "WS2812C-2020-V1" LED-SMD_4P-L2.0-W2.0-TL_WS2812B-2020 5323.98,4994.84 r180 top
LED178 "WS2812C-2020-V1" LED-SMD_4P-L2.0-W2.0-TL_WS2812B-2020 5461.77,4994.84 r180 top
LED179 "WS2812C-2020-V1" LED-SMD_4P-L2.0-W2.0-TL_WS2812B-2020 5599.57,4994.84 r180 top
LED180 "WS2812C-2020-V1" LED-SMD_4P-L2.0-W2.0-TL_WS2812B-2020 5737.36,4994.84 r180 top
LED181 "WS2812C-2020-V1" LED-SMD_4P-L2.0-W2.0-TL_WS2812B-2020 5875.16,4994.84 r180 top
LED182 "WS2812C-2020-V1" LED-SMD_4P-L2.0-W2.0-TL_WS2812B-2020 6012.95,4994.84 r180 top
LED183 "WS2812C-2020-V1" LED-SMD_4P-L2.0-W2.0-TL_WS2812B-2020 6150.75,4994.84 r180 top
LED184 "WS2812C-2020-V1" LED-SMD_4P-L2.0-W2.0-TL_WS2812B-2020 6288.54,4994.84 r180 top
LED185 "WS2812C-2020-V1" LED-SMD_4P-L2.0-W2.0-TL_WS2812B-2020 6426.34,4994.84 r180 top
LED186 "WS2812C-2020-V1" LED-SMD_4P-L2.0-W2.0-TL_WS2812B-2020 6564.13,4994.84 r180 top
LED187 "WS2812C-2020-V1" LED-SMD_4P-L2.0-W2.0-TL_WS2812B-2020 6701.93,4994.84 r180 top
LED188 "WS2812C-2020-V1" LED-SMD_4P-L2.0-W2.0-TL_WS2812B-2020 6839.72,4994.84 r180 top
LED189 "WS2812C-2020-V1" LED-SMD_4P-L2.0-W2.0-TL_WS2812B-2020 6977.52,4994.84 r180 top
LED190 "WS2812C-2020-V1" LED-SMD_4P-L2.0-W2.0-TL_WS2812B-2020 3915.6,6484.95 r255 top
LED191 "WS2812C-2020-V1" LED-SMD_4P-L2.0-W2.0-TL_WS2812B-2020 3950,6620 r256.53 top
LED192 "WS2812C-2020-V1" LED-SMD_4P-L2.0-W2.0-TL_WS2812B-2020 4772.8,4857.05 r180 top
LED193 "WS2812C-2020-V1" LED-SMD_4P-L2.0-W2.0-TL_WS2812B-2020 4910.59,4857.05 r180 top
LED194 "WS2812C-2020-V1" LED-SMD_4P-L2.0-W2.0-TL_WS2812B-2020 5048.39,4857.05 r180 top
LED195 "WS2812C-2020-V1" LED-SMD_4P-L2.0-W2.0-TL_WS2812B-2020 5186.18,4857.05 r180 top
LED196 "WS2812C-2020-V1" LED-SMD_4P-L2.0-W2.0-TL_WS2812B-2020 5323.98,4857.05 r180 top
LED197 "WS2812C-2020-V1" LED-SMD_4P-L2.0-W2.0-TL_WS2812B-2020 5461.77,4857.05 r180 top
LED198 "WS2812C-2020-V1" LED-SMD_4P-L2.0-W2.0-TL_WS2812B-2020 5599.57,4857.05 r180 top
LED199 "WS2812C-2020-V1" LED-SMD_4P-L2.0-W2.0-TL_WS2812B-2020 5737.36,4857.05 r180 top
LED200 "WS2812C-2020-V1" LED-SMD_4P-L2.0-W2.0-TL_WS2812B-2020 5875.16,4857.05 r180 top
LED201 "WS2812C-2020-V1" LED-SMD_4P-L2.0-W2.0-TL_WS2812B-2020 6012.95,4857.05 r180 top
LED202 "WS2812C-2020-V1" LED-SMD_4P-L2.0-W2.0-TL_WS2812B-2020 6150.75,4857.05 r180 top
LED203 "WS2812C-2020-V1" LED-SMD_4P-L2.0-W2.0-TL_WS2812B-2020 6288.54,4857.05 r180 top
LED204 "WS2812C-2020-V1" LED-SMD_4P-L2.0-W2.0-TL_WS2812B-2020 6426.34,4857.05 r180 top
LED205 "WS2812C-2020-V1" LED-SMD_4P-L2.0-W2.0-TL_WS2812B-2020 6564.13,4857.05 r180 top
LED206 "WS2812C-2020-V1" LED-SMD_4P-L2.0-W2.0-TL_WS2812B-2020 6701.93,4857.05 r180 top
LED207 "WS2812C-2020-V1" LED-SMD_4P-L2.0-W2.0-TL_WS2812B-2020 6839.72,4857.05 r180 top
LED208 "WS2812C-2020-V1" LED-SMD_4P-L2.0-W2.0-TL_WS2812B-2020 3845.53,7518.79 r246.96 top
LED209 "WS2812C-2020-V1" LED-SMD_4P-L2.0-W2.0-TL_WS2812B-2020 3899.47,7645.59 r246.96 top
LED210 "WS2812C-2020-V1" LED-SMD_4P-L2.0-W2.0-TL_WS2812B-2020 3956.72,7773.04 r246.96 top
LED211 "WS2812C-2020-V1" LED-SMD_4P-L2.0-W2.0-TL_WS2812B-2020 4010.66,7899.84 r246.96 top
LED212 "WS2812C-2020-V1" LED-SMD_4P-L2.0-W2.0-TL_WS2812B-2020 4064.59,8026.64 r246.96 top
LED213 "WS2812C-2020-V1" LED-SMD_4P-L2.0-W2.0-TL_WS2812B-2020 4118.53,8153.44 r246.96 top
LED214 "WS2812C-2020-V1" LED-SMD_4P-L2.0-W2.0-TL_WS2812B-2020 4172.47,8280.24 r246.96 top
Q1 "BSS138_C489349" SOT-23-3_L2.9-W1.3-P1.90-LS2.4-BR 6420,6410 r180 top
Q2 "L8050QLT1G" SOT-23-3_L2.9-W1.3-P1.90-LS2.4-BR 4770,7115 r90 top
Q3 "L8050QLT1G" SOT-23-3_L2.9-W1.3-P1.90-LS2.4-BR 4765,7340 r270 top
R1 "0603WAJ0102T5E" R0603 6300,6415 r90 top
R2 "0603WAJ0102T5E" R0603 6535,6370 r270 top
R3 "0603WAF1501T5E" R0603 6360,6800 r0 top
R7 "0402WGF1002TCE" R0402 4515,7500 r317.36 top
R8 "0402WGF1002TCE" R0402 4270,7710 r136.47 top
R9 "0603WAF0000T5E" R0603 5025,7000 r180 top
R10 "0603WAF0000T5E" R0603 5025,7125 r180 top
R11 "0603WAF0000T5E" R0603 5025,7250 r180 top
R12 "0603WAF0000T5E" R0603 5025,7375 r180 top
R13 "0402WGF1002TCE" R0402 4810,7225 r90 top
R14 "0402WGF1002TCE" R0402 4730,7225 r270 top
R15 "0402WGF1101TCE" R0402 4175,7615 r46.97 top
R16 "0603WAF2202T5E" R0603 4454.29,6824.29 r0 top
R17 "RC0603FR-07100KL" R0603 4574.29,6824.29 r0 top
R18 "0603WAF1501T5E" R0603 5245,7165 r180 top
R19 "0603WAF1501T5E" R0603 5245,7000 r180 top
R20 "0603WAF0000T5E" R0603 4300,6705 r90 top
U1 "ESP-12F(ESP8266MOD)" WIFIM-SMD_ESP-12F-ESP8266MOD 5715,6860 r269.93 top
U2 "CP2102N-A02-GQFN24R" QFN-24_L4.0-W4.0-P0.50-TL-EP2.6 4275,7470 r230.03 top
U3 "ZD8028IB5TR" SOT-23-5_L2.9-W1.6-P0.95-LS2.9-BL 4499.29,7054.29 r180 top
USB1 "TYPE-C 16PIN 2MD(073)" USB-C-SMD_TYPE-C-6PIN-2MD-073 4495,7720 r140.54 top

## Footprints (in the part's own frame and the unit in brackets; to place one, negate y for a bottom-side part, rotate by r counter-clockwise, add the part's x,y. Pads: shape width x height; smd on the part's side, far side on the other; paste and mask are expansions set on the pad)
C0402 [mm]
  rect 0.79x0.54 smd: 1(-0.545,0) 2(0.545,0)
  silkscreen extent -1.17,-0.5 1.17,0.5
C0603 [mm]
  rect 0.8x0.9 smd: 1(-0.7,0) 2(0.7,0)
  silkscreen extent -1.41,-0.71 1.39,0.72
C0805 [mm]
  rect 1.41x1.35 smd: 1(-1.03,0) 2(1.03,0)
  silkscreen extent -1.96,-0.9 1.96,0.9
HDR-TH_6P-P2.54-V-M-R2-C3-S2.54-1 [mm]
  rect 1.8x1.8 hole 1.05: 1(-2.54,-1.27)
  round 1.8 hole 1.05: 2(-2.54,1.27) 3(0,-1.27) 4(0,1.27) 5(2.54,-1.27) 6(2.54,1.27)
  silkscreen extent -3.81,-2.54 3.81,2.54
HDR-TH_10P-P2.54-V-M-R2-C5-S2.54 [mm]
  rect 1.7x1.7 hole 1.1: 1(-5.08,-1.27)
  round 1.7 hole 1.1: 2(-5.08,1.27) 3(-2.54,-1.27) 4(-2.54,1.27) 5(0,-1.27) 6(0,1.27) 7(2.54,-1.27) 8(2.54,1.27) 9(5.08,-1.27) 10(5.08,1.27)
  silkscreen extent -6.35,-2.54 6.35,2.54
IMPORTED_IMAGE [mil]
IND-SMD_L2.0-W1.6_MHCHL201610A-1R0M-Q8A [mm]
  rect 0.8x2 smd: 1(-0.9,0) 2(0.9,0)
  silkscreen extent -0.46,-1.14 0.46,1.14
LED-SMD_4P-L2.0-W2.0-TL_WS2812B-2020 [mm]
  rect 0.9x0.7 smd: 1(-0.915,0.55) 2(-0.915,-0.55) 3(0.915,-0.55) 4(0.915,0.55)
  silkscreen extent -1.3,-1.1 1,1.15
QFN-24_L4.0-W4.0-P0.50-TL-EP2.6 [mm]
  oval 0.8x0.28 smd: 1(-2,1.25) 2(-2,0.75) 3(-2,0.25) 4(-2,-0.25) 5(-2,-0.75) 6(-2,-1.25) 13(2,-1.25) 14(2,-0.75) 15(2,-0.25) 16(2,0.25) 17(2,0.75) 18(2,1.242)
  oval 0.28x0.8 smd: 7(-1.25,-2) 8(-0.75,-2) 9(-0.25,-2) 10(0.25,-2) 11(0.75,-2) 12(1.25,-2) 19(1.25,2) 20(0.75,2) 21(0.25,2) 22(-0.25,2) 23(-0.75,2) 24(-1.25,2)
  rect 2.7x2.7 smd: 25(0,-0.013)
  silkscreen extent -3.05,-2.16 2.15,2.14
R0402 [mm]
  rect 0.566x0.54 smd: 1(-0.433,0) 2(0.433,0)
  silkscreen extent -0.94,-0.5 0.94,0.5
R0603 [mil]
  rect 31.75x34.02 smd: 1(-29.66,0) 2(29.66,0)
  silkscreen extent -55,-26 55,26
SOT-23-3_L2.9-W1.3-P1.90-LS2.4-BR [mm]
  rect 1.25x0.7 smd: 1(1,-0.95) 2(1,0.95) 3(-1,0)
  silkscreen extent -0.73,-1.53 0.73,1.53
SOT-23-5_L2.9-W1.6-P0.95-LS2.9-BL [mm]
  rect 0.6x1 smd: 1(-0.95,-1.1) 2(0,-1.1) 3(0.95,-1.1) 4(0.95,1.1) 5(-0.95,1.1)
  silkscreen extent -1.45,-0.8 1.45,0.8
SW-SMD_4P-L6.0-W6.0-P4.50-LS9.0-2 [mm]
  rect 2.3x1.5 smd: 1(-4.55,2.25) 2(4.55,2.25) 3(-4.55,-2.25) 4(4.55,-2.25)
  silkscreen extent -3,-3 3,3
USB-C-SMD_TYPE-C-6PIN-2MD-073 [mm]
  rect 0.55x1.1 smd: 1(-3.2,2.375) 2(-2.4,2.375) 11(2.4,2.375) 12(3.2,2.375)
  rect 0.3x1.1 smd: 3(-1.75,2.375) 4(-1.25,2.375) 5(-0.75,2.375) 6(-0.25,2.375) 7(0.25,2.375) 8(0.75,2.375) 9(1.25,2.375) 10(1.75,2.375)
  oval 1.1x2 hole 0.6 slot 1.5 at 90 deg: 13(-4.325,1.825) 14(4.325,1.825)
  oval 1.2x1.8 hole 0.6 slot 1.2 at 90 deg: 13(-4.325,-2.375) 14(4.325,-2.375)
  Multi-Layer board cut-out: -3.16,1.082 -3.013,0.981 -2.834,0.965 -2.672,1.04 -2.567,1.185 -2.548,1.363 -2.62,1.527 -2.62,1.527 -2.767,1.629 -2.945,1.645 -3.108,1.57 -3.213,1.425 -3.232,1.247 -3.16,1.082
  Multi-Layer board cut-out: 2.62,1.082 2.767,0.979 2.946,0.963 3.11,1.038 3.215,1.184 3.233,1.363 3.16,1.527 3.16,1.527 3.013,1.63 2.834,1.647 2.67,1.572 2.565,1.426 2.547,1.247 2.62,1.082
  silkscreen extent -4.5,-4.97 4.57,0.6
WIFIM-SMD_ESP-12F-ESP8266MOD [mm]
  rect 1.4x2.5 smd: 1(-7.651,-7.551) 2(-5.651,-7.551) 3(-3.651,-7.551) 4(-1.651,-7.551) 5(0.349,-7.551) 6(2.349,-7.551) 7(4.349,-7.551) 8(6.349,-7.551) 9(6.349,7.549) 10(4.349,7.55) 11(2.349,7.551) 12(0.349,7.551) 13(-1.651,7.55) 14(-3.651,7.551) 15(-5.651,7.55) 16(-7.651,7.551)
  rect 1.7x1.4 smd: 17(7.651,-5) 18(7.649,-3.002) 19(7.65,-1.003) 20(7.65,0.997) 21(7.65,2.997) 22(7.65,4.997)
  silkscreen extent -16.15,-8.92 7.85,8

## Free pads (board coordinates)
  round 236.22 hole 157.48: 26(4191.46,8586.89) 26(7290,8760)
  round 0.1 hole 23.62 unplated: 27(4338.14,8681.15) 27(4355.6,8647.49)
  round 0.1 hole 23.62: 28(4363.28,8613.39) 29(4366.24,8578.66) 29(4699.17,4401.62) 29(4722.5,4370.34) 29(4938.35,4085.51) 30(4366.24,8539.29) 30(4751.18,4340.58) 31(4366.24,8499.92) 31(4776.05,4311.46) 32(4366.24,8460.55) 32(4799.66,4281.71) 33(4366.24,8421.18) 33(4825.17,4250.05) 34(4366.24,8381.81) 34(4848.77,4217.76) 35(4366.24,8342.44) 35(4871.74,4186.73) 36(4366.24,8303.07) 36(4894.71,4156.34) 37(4366.24,8263.7) 37(4916.41,4122.14)

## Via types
v1: diameter 24.02, hole 12.01, Top Layer to Bottom Layer, 504 vias
v2: diameter 23.62, hole 12.01, Top Layer to Bottom Layer, 1 vias

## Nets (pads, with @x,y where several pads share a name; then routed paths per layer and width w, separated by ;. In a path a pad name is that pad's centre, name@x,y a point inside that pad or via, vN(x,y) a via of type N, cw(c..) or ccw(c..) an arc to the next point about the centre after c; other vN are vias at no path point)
$1N106302: R8.2 USB1.10 | length 240.8
  Top Layer w10: v1(4245,7760) 4257.65,7747.35 R8.2@4257.65,7721.74 ; v1(4360,7660) 4360,7669.22 USB1.10@4382.38,7691.6
  Bottom Layer w10: v1(4245,7760) 4345,7660 v1(4360,7660)
$1N106306: R7.2 USB1.4 | length 273.8
  Top Layer w10: v1(4445,7580) 4445,7587.97 USB1.4@4473.57,7616.54 ; R7.2@4527.53,7488.46 4573.46,7488.46 v1(4580,7495)
  Bottom Layer w10: v1(4445,7580) 4530,7495 v1(4580,7495)
$1N108491: U2.3 USB1.6 USB1.8 | length 328.9
  Top Layer w10: U2.3@4333.11,7524.03 4419.86,7610.77 4419.86,7616.08 4443.18,7639.4 USB1.6@4443.18,7641.55 4476.63,7675 v1(4490,7675) ; USB1.8@4412.78,7666.57 4440,7693.79 v1(4440,7700)
  Bottom Layer w10: v1(4440,7700) 4465,7700 v1(4490,7675)
$1N108504: U2.4 USB1.5 USB1.7 | length 368.4
  Top Layer w10: U2.4@4318.03,7536.67 4404.65,7623.29 4404.65,7628.59 4427.98,7651.91 USB1.7@4427.98,7654.06 4428.89,7654.06 4447.83,7673 4454.81,7673 4470.82,7689.02 4471.5,7689.02 4480.48,7697.99 4499.52,7697.99 4512.99,7684.52 4512.99,7665.48 4499.52,7652.01 4480.48,7652.01 4476.97,7655.52 4472.48,7651.03 4472.48,7644.05 4457.92,7629.49 USB1.5@4458.37,7629.04
$1N108805: Q2.1 R13.1 | length 54.7
  Top Layer w20: Q2.1@4807.4,7154.37 4810,7156.97 R13.1@4810,7207.96
$1N108844: Q3.1 R14.1 | length 59.6
  Top Layer w20: Q3.1@4727.6,7300.63 4730,7298.23 R14.1@4730,7242.04
$1N108927: Q3.3 R12.2 | length 232.2
  Top Layer w10: Q3.3@4765,7379.37 4990.97,7379.37 R12.2@4995.34,7375
$1N108929: Q2.3 R11.2 | length 297.6
  Top Layer w10: Q2.3@4770,7075.63 4820.97,7075.63 R11.2@4995.34,7250
$1N110371: Q2.2 R14.2 U2.19 | length 617.5
  Top Layer w10: U2.19@4303.73,7381.71 4303.73,7356.27 v1(4310,7350)
  Top Layer w20: v1(4680,7210) 4682.04,7207.96 R14.2@4730,7207.96 4732.6,7205.36 Q2.2@4732.6,7154.37
  Bottom Layer w10: v1(4310,7350) 4355,7305 4405,7305 4465,7365 4525,7365 v1(4680,7210)
$1N110652: R10.2 U2.21 | length 1023.1
  Top Layer w10: U2.21@4329.02,7411.88 4333.98,7411.88 4350.86,7395 v1(4360,7395) ; v1(4805,7000) 4870.34,7000 R10.2@4995.34,7125
  Bottom Layer w10: v1(4360,7395) 4366.99,7401.99 4431.99,7401.99 4445,7415 4570,7415 4820,7165 4820,7015 v1(4805,7000)
$1N110666: R9.2 U2.20 | length 1002.9
  Top Layer w10: U2.20@4316.37,7396.79 4340,7373.16 v1(4340,7370) ; v1(4775,6960) 4955.34,6960 R9.2@4995.34,7000
  Bottom Layer w10: v1(4340,7370) 4450.18,7370 4459.19,7379.02 4555.98,7379.02 4765,7170 4765,6970 v1(4775,6960)
$1N110677: Q3.2 R13.2 U2.23 | length 670.9
  Top Layer w10: U2.23@4354.31,7442.05 4371.36,7425 v1(4385,7425)
  Top Layer w20: Q3.2@4802.4,7300.63 4810,7293.03 Q3.2@4810,7284.79 ; R13.2@4810,7242.04 Q3.2@4810,7284.79 ; v1(4850,7285) 4810.21,7285 Q3.2@4810,7284.79
  Bottom Layer w10: v1(4385,7425) 4395,7435 4700,7435 v1(4850,7285)
$1N110800: R15.1 U2.9 | length 98.3
  Top Layer w10: R15.1@4163.37,7602.54 4180,7585.92 4180,7569.08 U2.9@4220.97,7528.12
$1N111216: L1.1 U3.3 | length 128.2
  Top Layer w20: U3.3@4461.89,7097.6 4461.89,7152.32 L1.1@4513.86,7204.29
$1N114236: C232.1 R16.2 R17.1 U3.5 | length 250.7
  Top Layer w20: R16.2@4483.95,6824.29 R17.1@4544.63,6824.29 4541.73,6827.19 C232.1@4541.73,6934.29 4536.69,6939.32 U3.5@4536.69,7010.98
$2N19971: LED1.1 LED2.3 | length 1279.4
  Top Layer w10: LED2.3@7316.77,7661.65 7316.77,8221.77 7755,8660 7755,8720 7741.65,8733.34 LED1.1@7721.02,8733.34
$2N20220: LED2.1 LED3.3 | length 3940.4
  Top Layer w10: LED3.3@4874.57,6256.65 4917.91,6300 7355,6300 7420,6365 7420,6480 7440,6500 7440,6810.02 7380,6870.02 7380,7015 7445,7080 7445,7585 7411.65,7618.35 LED2.1@7388.82,7618.35
$2N20224: LED3.1 LED4.3 | length 83.7
  Top Layer w10: LED3.1@4946.62,6213.35 4965.11,6213.35 5008.42,6256.65 LED4.3@5012.36,6256.65
$2N20228: LED4.1 LED5.3 | length 83.7
  Top Layer w10: LED4.1@5084.41,6213.35 5102.91,6213.35 5146.22,6256.65 LED5.3@5150.16,6256.65
$2N20232: LED5.1 LED6.3 | length 83.7
  Top Layer w10: LED5.1@5222.21,6213.35 5240.7,6213.35 5284.01,6256.65 LED6.3@5287.95,6256.65
$2N20236: LED6.1 LED7.3 | length 83.7
  Top Layer w10: LED6.1@5360,6213.35 5369.09,6213.35 5412.4,6256.65 LED7.3@5425.75,6256.65
$2N20240: LED7.1 LED8.3 | length 83.7
  Top Layer w10: LED7.1@5497.8,6213.35 5506.89,6213.35 5550.2,6256.65 LED8.3@5563.54,6256.65
$2N20244: LED8.1 LED9.3 | length 83.7
  Top Layer w10: LED8.1@5635.59,6213.35 5644.68,6213.35 5687.99,6256.65 LED9.3@5701.34,6256.65
$2N20248: LED9.1 LED10.3 | length 83.7
  Top Layer w10: LED9.1@5773.39,6213.35 5782.48,6213.35 5825.79,6256.65 LED10.3@5839.13,6256.65
$2N20252: LED10.1 LED11.3 | length 83.7
  Top Layer w10: LED10.1@5911.18,6213.35 5920.28,6213.35 5963.59,6256.65 LED11.3@5976.93,6256.65
$2N20256: LED11.1 LED12.3 | length 83.7
  Top Layer w10: LED11.1@6048.98,6213.35 6058.07,6213.35 6101.38,6256.65 LED12.3@6114.72,6256.65
$2N20260: LED12.1 LED13.3 | length 83.7
  Top Layer w10: LED12.1@6186.77,6213.35 6195.87,6213.35 6239.18,6256.65 LED13.3@6252.52,6256.65
$2N20264: LED13.1 LED14.3 | length 83.7
  Top Layer w10: LED13.1@6324.57,6213.35 6333.66,6213.35 6376.97,6256.65 LED14.3@6390.31,6256.65
$2N20268: LED14.1 LED15.3 | length 83.7
  Top Layer w10: LED14.1@6462.36,6213.35 6471.46,6213.35 6514.77,6256.65 LED15.3@6528.11,6256.65
$2N20272: LED15.1 LED16.3 | length 83.7
  Top Layer w10: LED15.1@6600.16,6213.35 6613.5,6213.35 6656.81,6256.65 LED16.3@6665.9,6256.65
$2N20276: LED16.1 LED17.3 | length 3994.2
  Top Layer w10: LED17.3@3669.8,5829.79 3669.8,5805.55 3700,5775.35 v1(3700,5765) ; LED16.1@6737.95,6213.35 6803.35,6213.35 v1(6805,6215)
  Bottom Layer w10: v1(3700,5765) 3710,5755 3935,5755 4120,5940 4120,6175 4310,6365 6886.28,6365 6925,6326.28 6925,6245 6895,6215 v1(6805,6215)
$2N20280: LED17.1 LED18.3 | length 86.6
  Top Layer w10: LED18.3@3724.81,5958.65 3724.81,5934.29 3738.81,5920.29 LED17.1@3738.81,5877.89
$2N20284: LED18.1 LED19.3 | length 80.5
  Top Layer w10: LED19.3@3773.26,6077.36 3773.26,6057.69 3794.26,6036.69 LED18.1@3794.26,6005.58
$2N20288: LED19.1 LED20.3 | length 823.3
  Top Layer w10: LED19.1@3844.78,6137.47 3860,6152.68 3860,6155 3890,6155 v1(3895,6160) ; v1(4050,6125) 4056.14,6118.86 LED20.3@4598.98,6118.86
  Bottom Layer w10: v1(3895,6160) 3905,6160 3990,6075 4000,6075 v1(4050,6125)
$2N20292: LED20.1 LED21.3 | length 83.7
  Top Layer w10: LED20.1@4671.02,6075.55 4684.37,6075.55 4727.68,6118.86 LED21.3@4736.77,6118.86
$2N20296: LED21.1 LED22.3 | length 83.7
  Top Layer w10: LED21.1@4808.82,6075.55 4822.16,6075.55 4865.47,6118.86 LED22.3@4874.57,6118.86
$2N20300: LED22.1 LED23.3 | length 83.7
  Top Layer w10: LED22.1@4946.62,6075.55 4959.96,6075.55 5003.27,6118.86 LED23.3@5012.36,6118.86
$2N20304: LED23.1 LED24.3 | length 83.7
  Top Layer w10: LED23.1@5084.41,6075.55 5097.75,6075.55 5141.06,6118.86 LED24.3@5150.16,6118.86
$2N20308: LED24.1 LED25.3 | length 83.7
  Top Layer w10: LED24.1@5222.21,6075.55 5235.55,6075.55 5278.86,6118.86 LED25.3@5287.95,6118.86
$2N20312: LED26.1 LED27.3 | length 83.7
  Top Layer w10: LED26.1@5497.8,6075.55 5506.89,6075.55 5550.2,6118.86 LED27.3@5563.54,6118.86
$2N20570: LED27.1 LED28.3 | length 83.7
  Top Layer w10: LED27.1@5635.59,6075.55 5644.68,6075.55 5687.99,6118.86 LED28.3@5701.34,6118.86
$2N20574: LED28.1 LED29.3 | length 83.7
  Top Layer w10: LED28.1@5773.39,6075.55 5782.48,6075.55 5825.79,6118.86 LED29.3@5839.13,6118.86
$2N20578: LED29.1 LED30.3 | length 83.7
  Top Layer w10: LED29.1@5911.18,6075.55 5920.28,6075.55 5963.59,6118.86 LED30.3@5976.93,6118.86
$2N20582: LED30.1 LED31.3 | length 83.7
  Top Layer w10: LED30.1@6048.98,6075.55 6058.07,6075.55 6101.38,6118.86 LED31.3@6114.72,6118.86
$2N20586: LED31.1 LED32.3 | length 83.7
  Top Layer w10: LED31.1@6186.77,6075.55 6195.87,6075.55 6239.18,6118.86 LED32.3@6252.52,6118.86
$2N20590: LED32.1 LED33.3 | length 83.7
  Top Layer w10: LED32.1@6324.57,6075.55 6333.66,6075.55 6376.97,6118.86 LED33.3@6390.31,6118.86
$2N20594: LED33.1 LED34.3 | length 83.7
  Top Layer w10: LED33.1@6462.36,6075.55 6471.46,6075.55 6514.77,6118.86 LED34.3@6528.11,6118.86
$2N20598: LED34.1 LED35.3 | length 83.7
  Top Layer w10: LED34.1@6600.16,6075.55 6609.25,6075.55 6652.56,6118.86 LED35.3@6665.9,6118.86
$2N20602: LED35.1 LED36.3 | length 83.7
  Top Layer w10: LED35.1@6737.95,6075.55 6747.05,6075.55 6790.36,6118.86 LED36.3@6803.7,6118.86
$2N20606: LED36.1 LED37.3 | length 83.7
  Top Layer w10: LED36.1@6875.75,6075.55 6884.84,6075.55 6928.15,6118.86 LED37.3@6941.49,6118.86
$2N20610: LED37.1 LED38.3 | length 3412.2
  Top Layer w10: v1(3760,6215) 3809.57,6215 LED38.3@3820.64,6203.93 ; v1(3995,6200) 4217.48,6200 4220.48,6197.01 4642.01,6197.01 v1(4685,6240)
  Bottom Layer w10: v1(3760,6215) 3980,6215 v1(3995,6200) ; v1(4685,6240) 4825,6100 6989.09,6100 v1(7013.54,6075.55)
$2N20614: LED38.1 LED39.3 | length 992.1
  Top Layer w10: LED38.1@3881.12,6262.32 3901.41,6262.32 3919.1,6280 v1(3930,6280) ; v1(4070,5995) 4585.04,5995 LED39.3@4598.98,5981.06
  Bottom Layer w10: v1(3930,6280) 4025,6280 4072.99,6232.01 4072.99,5997.99 v1(4070,5995)
$2N20618: LED39.1 LED40.3 | length 83.7
  Top Layer w10: LED39.1@4671.02,5937.75 4680.12,5937.75 4723.43,5981.06 LED40.3@4736.77,5981.06
$2N20622: LED40.1 LED41.3 | length 83.7
  Top Layer w10: LED40.1@4808.82,5937.75 4817.91,5937.75 4861.22,5981.06 LED41.3@4874.57,5981.06
$2N20626: LED41.1 LED42.3 | length 83.7
  Top Layer w10: LED41.1@4946.62,5937.75 4955.71,5937.75 4999.02,5981.06 LED42.3@5012.36,5981.06
$2N20630: LED42.1 LED43.3 | length 83.7
  Top Layer w10: LED42.1@5084.41,5937.75 5093.5,5937.75 5136.81,5981.06 LED43.3@5150.16,5981.06
$2N20634: LED43.1 LED44.3 | length 83.7
  Top Layer w10: LED43.1@5222.21,5937.75 5231.3,5937.75 5274.61,5981.06 LED44.3@5287.95,5981.06
$2N20638: LED44.1 LED45.3 | length 83.7
  Top Layer w10: LED44.1@5360,5937.75 5369.09,5937.75 5412.4,5981.06 LED45.3@5425.75,5981.06
$2N20642: LED45.1 LED46.3 | length 83.7
  Top Layer w10: LED45.1@5497.8,5937.75 5506.89,5937.75 5550.2,5981.06 LED46.3@5563.54,5981.06
$2N20646: LED46.1 LED47.3 | length 83.7
  Top Layer w10: LED46.1@5635.59,5937.75 5644.68,5937.75 5687.99,5981.06 LED47.3@5701.34,5981.06
$2N20650: LED47.1 LED48.3 | length 83.7
  Top Layer w10: LED47.1@5773.39,5937.75 5782.48,5937.75 5825.79,5981.06 LED48.3@5839.13,5981.06
$2N20654: LED48.1 LED49.3 | length 83.7
  Top Layer w10: LED48.1@5911.18,5937.75 5920.28,5937.75 5963.59,5981.06 LED49.3@5976.93,5981.06
$2N20658: LED49.1 LED50.3 | length 83.7
  Top Layer w10: LED49.1@6048.98,5937.75 6058.07,5937.75 6101.38,5981.06 LED50.3@6114.72,5981.06
$2N20662: LED51.1 LED52.3 | length 83.7
  Top Layer w10: LED51.1@6324.57,5937.75 6333.66,5937.75 6376.97,5981.06 LED52.3@6390.31,5981.06
$2N20920: LED52.1 LED53.3 | length 83.7
  Top Layer w10: LED52.1@6462.36,5937.75 6471.46,5937.75 6514.77,5981.06 LED53.3@6528.11,5981.06
$2N20924: LED53.1 LED54.3 | length 83.7
  Top Layer w10: LED53.1@6600.16,5937.75 6609.25,5937.75 6652.56,5981.06 LED54.3@6665.9,5981.06
$2N20928: LED54.1 LED55.3 | length 83.7
  Top Layer w10: LED54.1@6737.95,5937.75 6747.05,5937.75 6790.36,5981.06 LED55.3@6803.7,5981.06
$2N20932: LED55.1 LED56.3 | length 83.7
  Top Layer w10: LED55.1@6875.75,5937.75 6884.84,5937.75 6928.15,5981.06 LED56.3@6941.49,5981.06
